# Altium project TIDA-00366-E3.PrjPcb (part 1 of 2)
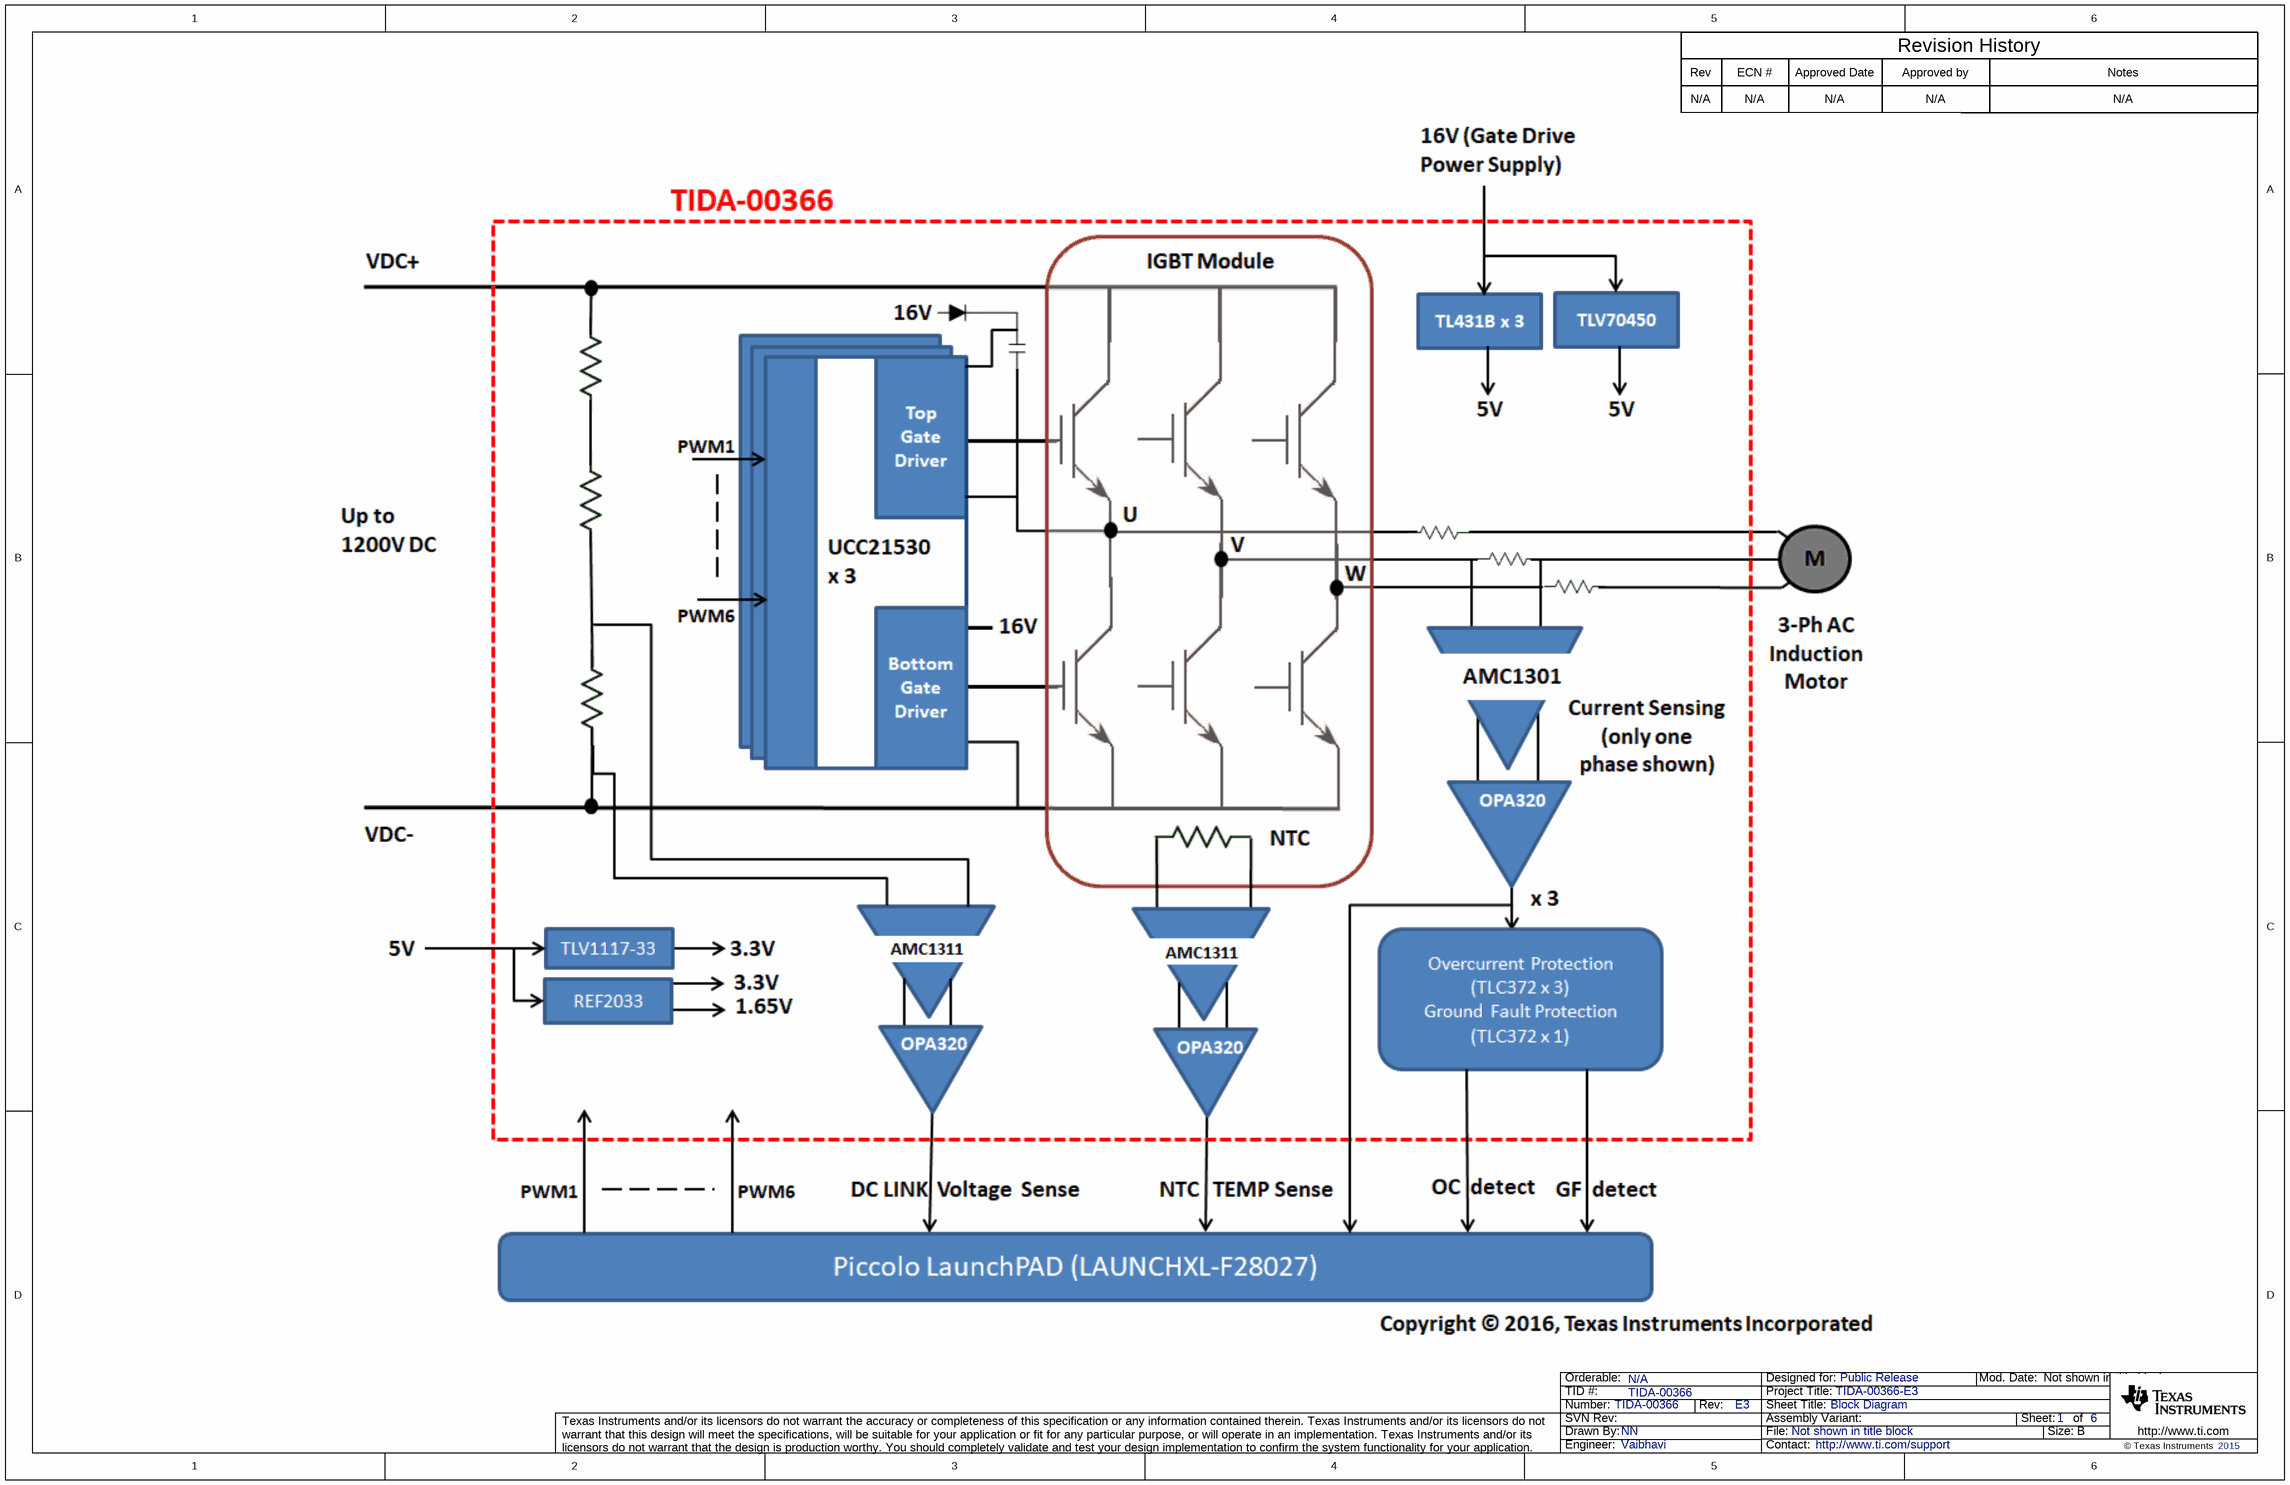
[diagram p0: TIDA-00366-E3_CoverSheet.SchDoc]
CopyrightYear: 2015; EVM_Orderable: N/A; PCB_Layout: Avinash N; PCB_Rev: E3; PRJ_Customer: Public Release; PRJ_Engineer: Vaibhavi; PRJ_Number: TIDA-00366; PRJ_Title: TIDA-00366-E3; SCH_Rev: E3; TechSupport: http://www.ti.com/support; TID: TIDA-00366
6 sheets, 363 parts. Net scope: flat (ports and power ports of the same name join across sheets).
Board file: TIDA-00366-E3.PcbDoc
Sheets:
  TIDA-00366-E3_CoverSheet.SchDoc
  TIDA-00366-E3_Current sense.SchDoc
  TIDA-00366-E3_Gate driver and Module.SchDoc
  TIDA-00366-E3_DC BUS and TEMP Sense.SchDoc
  TIDA-00366-E3_MCU Interface.SchDoc
  TIDA-00366-E3_EVM_Hardware.SchDoc

## Sheet TIDA-00366-E3_CoverSheet.SchDoc: Block Diagram
size 431 x 279 mm; Date: Not shown in title block; ApprovedBy: Not shown in title block; CheckedBy: Not shown in title block; Author: Not shown in title block; CompanyName: Not shown in title block; DrawnBy: NN; Engineer: Not shown in title block; Organization: Not shown in title block; Address1: Not shown in title block; Address2: Not shown in title block; Address3: Not shown in title block; Address4: Not shown in title block; DocumentNumber: 1; Revision: Use project parameter SCH_Rev; SheetNumber: 1; SheetTotal: 6; PageSetup: Record=PageOptions¦CenterHorizontal=True¦CenterVertical=True¦PrintScale=1.00¦XCorrection=1.00¦YCorrection=1.00¦PrintKind=0¦BorderSize=5000000¦LeftOffset=0¦BottomOffset=0¦Orientation=2¦PaperLength=1000¦PaperWidth=1000¦Scale=100¦PaperSource=15¦PrintQuality=600¦MediaType=1¦DitherType=10¦PaperKind=Letter¦PrintScaleMode=1

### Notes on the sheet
- Rev
- N/A
- ECN #
- Approved Date
- Approved by
- Revision History
- Notes

## Sheet TIDA-00366-E3_Current sense.SchDoc: Current Sense
size 431 x 279 mm; Date: Not shown in title block; ApprovedBy: Not shown in title block; CheckedBy: Not shown in title block; Author: Not shown in title block; CompanyName: Not shown in title block; DrawnBy: NN; Engineer: Not shown in title block; Organization: Not shown in title block; Address1: Not shown in title block; Address2: Not shown in title block; Address3: Not shown in title block; Address4: Not shown in title block; DocumentNumber: 1; Revision: Use project parameter SCH_Rev; SheetNumber: 3; SheetTotal: 6; PageSetup: Record=PageOptions¦CenterHorizontal=True¦CenterVertical=True¦PrintScale=1.00¦XCorrection=1.00¦YCorrection=1.00¦PrintKind=0¦BorderSize=5000000¦LeftOffset=0¦BottomOffset=0¦Orientation=2¦PaperLength=1000¦PaperWidth=1000¦Scale=100¦PaperSource=15¦PrintQuality=600¦MediaType=1¦DitherType=10¦PaperKind=Letter¦PrintScaleMode=1
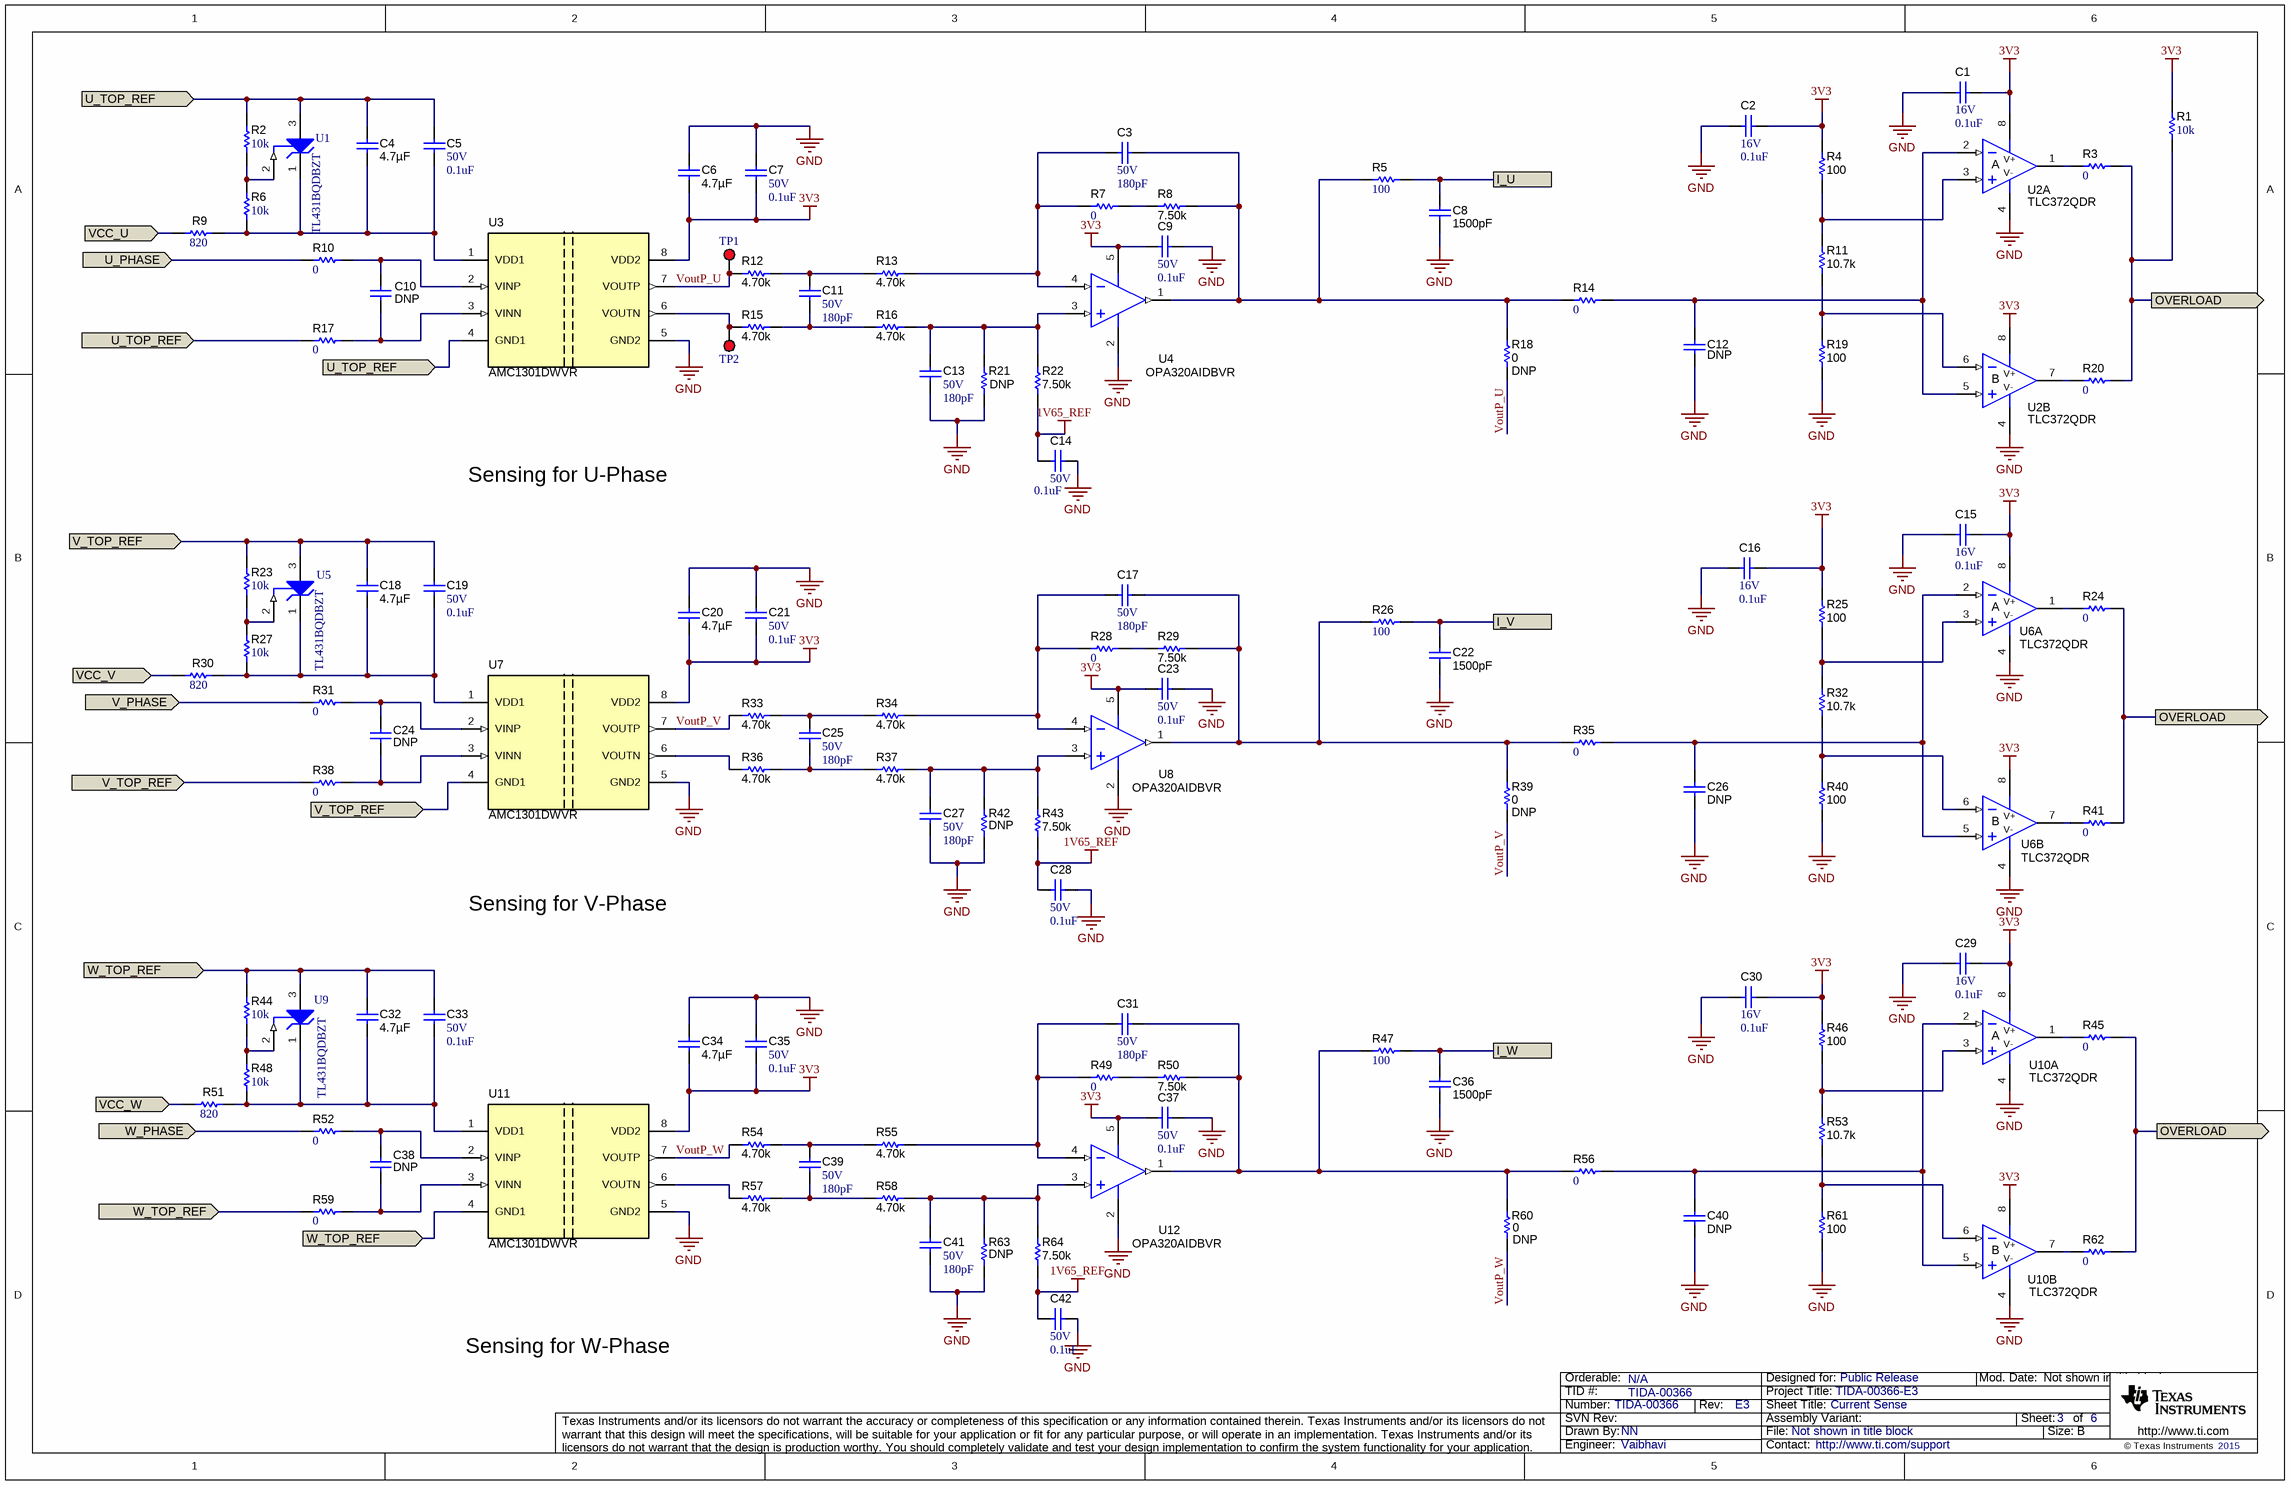
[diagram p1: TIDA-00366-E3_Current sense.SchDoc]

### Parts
C1  VDC_V: 16V  ValueDisplayed: 0.1uF  [0603]  (hidden comment: C0603X104K4RACTU)
C2  VDC_V: 16V  ValueDisplayed: 0.1uF  [0603]  (hidden comment: C0603X104K4RACTU)
C3  VDC_V: 50V  ValueDisplayed: 180pF  [0603]  (hidden comment: GRM1885C1H181JA01D)
C4  ValueDisplayed: 4.7µF  [0805_HV]  (hidden comment: C2012X5R1H475K125AB)
C5  VDC_V: 50V  ValueDisplayed: 0.1uF  [0603]  (hidden comment: GCM188R71H104KA57D)
C6  ValueDisplayed: 4.7µF  [0805_HV]  (hidden comment: C2012X5R1H475K125AB)
C7  VDC_V: 50V  ValueDisplayed: 0.1uF  [0603]  (hidden comment: GCM188R71H104KA57D)
C8  ValueDisplayed: 1500pF  [0603]  (hidden comment: 06031C152JAT2A)
C9  VDC_V: 50V  ValueDisplayed: 0.1uF  [0603]  (hidden comment: GCM188R71H104KA57D)
C10  885012206040  [0603]  (value not drawn)
C11  VDC_V: 50V  ValueDisplayed: 180pF  [0603]  (hidden comment: GRM1885C1H181JA01D)
C12  885012206040  [0603]  (value not drawn)
C13  VDC_V: 50V  ValueDisplayed: 180pF  [0603]  (hidden comment: GRM1885C1H181JA01D)
C14  VDC_V: 50V  ValueDisplayed: 0.1uF  [0603]  (hidden comment: GCM188R71H104KA57D)
C15  VDC_V: 16V  ValueDisplayed: 0.1uF  [0603]  (hidden comment: C0603X104K4RACTU)
C16  VDC_V: 16V  ValueDisplayed: 0.1uF  [0603]  (hidden comment: C0603X104K4RACTU)
C17  VDC_V: 50V  ValueDisplayed: 180pF  [0603]  (hidden comment: GRM1885C1H181JA01D)
C18  ValueDisplayed: 4.7µF  [0805_HV]  (hidden comment: C2012X5R1H475K125AB)
C19  VDC_V: 50V  ValueDisplayed: 0.1uF  [0603]  (hidden comment: GCM188R71H104KA57D)
C20  ValueDisplayed: 4.7µF  [0805_HV]  (hidden comment: C2012X5R1H475K125AB)
C21  VDC_V: 50V  ValueDisplayed: 0.1uF  [0603]  (hidden comment: GCM188R71H104KA57D)
C22  ValueDisplayed: 1500pF  [0603]  (hidden comment: 06031C152JAT2A)
C23  VDC_V: 50V  ValueDisplayed: 0.1uF  [0603]  (hidden comment: GCM188R71H104KA57D)
C24  885012206040  [0603]  (value not drawn)
C25  VDC_V: 50V  ValueDisplayed: 180pF  [0603]  (hidden comment: GRM1885C1H181JA01D)
C26  885012206040  [0603]  (value not drawn)
C27  VDC_V: 50V  ValueDisplayed: 180pF  [0603]  (hidden comment: GRM1885C1H181JA01D)
C28  VDC_V: 50V  ValueDisplayed: 0.1uF  [0603]  (hidden comment: GCM188R71H104KA57D)
C29  VDC_V: 16V  ValueDisplayed: 0.1uF  [0603]  (hidden comment: C0603X104K4RACTU)
C30  VDC_V: 16V  ValueDisplayed: 0.1uF  [0603]  (hidden comment: C0603X104K4RACTU)
C31  VDC_V: 50V  ValueDisplayed: 180pF  [0603]  (hidden comment: GRM1885C1H181JA01D)
C32  ValueDisplayed: 4.7µF  [0805_HV]  (hidden comment: C2012X5R1H475K125AB)
C33  VDC_V: 50V  ValueDisplayed: 0.1uF  [0603]  (hidden comment: GCM188R71H104KA57D)
C34  ValueDisplayed: 4.7µF  [0805_HV]  (hidden comment: C2012X5R1H475K125AB)
C35  VDC_V: 50V  ValueDisplayed: 0.1uF  [0603]  (hidden comment: GCM188R71H104KA57D)
C36  ValueDisplayed: 1500pF  [0603]  (hidden comment: 06031C152JAT2A)
C37  VDC_V: 50V  ValueDisplayed: 0.1uF  [0603]  (hidden comment: GCM188R71H104KA57D)
C38  885012206040  [0603]  (value not drawn)
C39  VDC_V: 50V  ValueDisplayed: 180pF  [0603]  (hidden comment: GRM1885C1H181JA01D)
C40  885012206040  [0603]  (value not drawn)
C41  VDC_V: 50V  ValueDisplayed: 180pF  [0603]  (hidden comment: GRM1885C1H181JA01D)
C42  VDC_V: 50V  ValueDisplayed: 0.1uF  [0603]  (hidden comment: GCM188R71H104KA57D)
R1  ValueDisplayed: 10k  [0603]  (hidden comment: RC0603JR-0710KL)
R2  ValueDisplayed: 10k  [0603]  (hidden comment: RC0603JR-0710KL)
R3  ValueDisplayed: 0  [0603]  (hidden comment: RC0603JR-070RL)
R4  ValueDisplayed: 100  [0603]  (hidden comment: ERA-3AEB101V)
R5  ValueDisplayed: 100  [0603]  (hidden comment: RC0603FR-07100RL)
R6  ValueDisplayed: 10k  [0603]  (hidden comment: RC0603JR-0710KL)
R7  ValueDisplayed: 0  [0603]  (hidden comment: RC0603JR-070RL)
R8  ValueDisplayed: 7.50k  [0603]  (hidden comment: ERJ-3EKF7501V)
R9  ValueDisplayed: 820  [1206]  (hidden comment: CRCW1206820RJNEA)
R10  ValueDisplayed: 0  [0603]  (hidden comment: RC0603JR-070RL)
R11  ValueDisplayed: 10.7k  [0603]  (hidden comment: RG1608P-1072-B-T5)
R12  ValueDisplayed: 4.70k  [0603]  (hidden comment: RC0603FR-074K7L)
R13  ValueDisplayed: 4.70k  [0603]  (hidden comment: RC0603FR-074K7L)
R14  ValueDisplayed: 0  [0603]  (hidden comment: RC0603JR-070RL)
R15  ValueDisplayed: 4.70k  [0603]  (hidden comment: RC0603FR-074K7L)
R16  ValueDisplayed: 4.70k  [0603]  (hidden comment: RC0603FR-074K7L)
R17  ValueDisplayed: 0  [0603]  (hidden comment: RC0603JR-070RL)
R18  ValueDisplayed: 0  [0603]  (hidden comment: CRCW06030000Z0EA)
R19  ValueDisplayed: 100  [0603]  (hidden comment: ERA-3AEB101V)
R20  ValueDisplayed: 0  [0603]  (hidden comment: RC0603JR-070RL)
R21  ERJ-3EKF7501V  [0603]  (value not drawn)
R22  ValueDisplayed: 7.50k  [0603]  (hidden comment: ERJ-3EKF7501V)
R23  ValueDisplayed: 10k  [0603]  (hidden comment: RC0603JR-0710KL)
R24  ValueDisplayed: 0  [0603]  (hidden comment: RC0603JR-070RL)
R25  ValueDisplayed: 100  [0603]  (hidden comment: ERA-3AEB101V)
R26  ValueDisplayed: 100  [0603]  (hidden comment: RC0603FR-07100RL)
R27  ValueDisplayed: 10k  [0603]  (hidden comment: RC0603JR-0710KL)
R28  ValueDisplayed: 0  [0603]  (hidden comment: RC0603JR-070RL)
R29  ValueDisplayed: 7.50k  [0603]  (hidden comment: ERJ-3EKF7501V)
R30  ValueDisplayed: 820  [1206]  (hidden comment: CRCW1206820RJNEA)
R31  ValueDisplayed: 0  [0603]  (hidden comment: RC0603JR-070RL)
R32  ValueDisplayed: 10.7k  [0603]  (hidden comment: RG1608P-1072-B-T5)
R33  ValueDisplayed: 4.70k  [0603]  (hidden comment: RC0603FR-074K7L)
R34  ValueDisplayed: 4.70k  [0603]  (hidden comment: RC0603FR-074K7L)
R35  ValueDisplayed: 0  [0603]  (hidden comment: RC0603JR-070RL)
R36  ValueDisplayed: 4.70k  [0603]  (hidden comment: RC0603FR-074K7L)
R37  ValueDisplayed: 4.70k  [0603]  (hidden comment: RC0603FR-074K7L)
R38  ValueDisplayed: 0  [0603]  (hidden comment: RC0603JR-070RL)
R39  ValueDisplayed: 0  [0603]  (hidden comment: CRCW06030000Z0EA)
R40  ValueDisplayed: 100  [0603]  (hidden comment: ERA-3AEB101V)
R41  ValueDisplayed: 0  [0603]  (hidden comment: RC0603JR-070RL)
R42  ERJ-3EKF7501V  [0603]  (value not drawn)
R43  ValueDisplayed: 7.50k  [0603]  (hidden comment: ERJ-3EKF7501V)
R44  ValueDisplayed: 10k  [0603]  (hidden comment: RC0603JR-0710KL)
R45  ValueDisplayed: 0  [0603]  (hidden comment: RC0603JR-070RL)
R46  ValueDisplayed: 100  [0603]  (hidden comment: ERA-3AEB101V)
R47  ValueDisplayed: 100  [0603]  (hidden comment: RC0603FR-07100RL)
R48  ValueDisplayed: 10k  [0603]  (hidden comment: RC0603JR-0710KL)
R49  ValueDisplayed: 0  [0603]  (hidden comment: RC0603JR-070RL)
R50  ValueDisplayed: 7.50k  [0603]  (hidden comment: ERJ-3EKF7501V)
R51  ValueDisplayed: 820  [1206]  (hidden comment: CRCW1206820RJNEA)
R52  ValueDisplayed: 0  [0603]  (hidden comment: RC0603JR-070RL)
R53  ValueDisplayed: 10.7k  [0603]  (hidden comment: RG1608P-1072-B-T5)
R54  ValueDisplayed: 4.70k  [0603]  (hidden comment: RC0603FR-074K7L)
R55  ValueDisplayed: 4.70k  [0603]  (hidden comment: RC0603FR-074K7L)
R56  ValueDisplayed: 0  [0603]  (hidden comment: RC0603JR-070RL)
R57  ValueDisplayed: 4.70k  [0603]  (hidden comment: RC0603FR-074K7L)
R58  ValueDisplayed: 4.70k  [0603]  (hidden comment: RC0603FR-074K7L)
R59  ValueDisplayed: 0  [0603]  (hidden comment: RC0603JR-070RL)
R60  ValueDisplayed: 0  [0603]  (hidden comment: CRCW06030000Z0EA)
R61  ValueDisplayed: 100  [0603]  (hidden comment: ERA-3AEB101V)
R62  ValueDisplayed: 0  [0603]  (hidden comment: RC0603JR-070RL)
R63  ERJ-3EKF7501V  [0603]  (value not drawn)
R64  ValueDisplayed: 7.50k  [0603]  (hidden comment: ERJ-3EKF7501V)
TP1  5000  [Keystone5000]  (value not drawn)
TP2  5000  [Keystone5000]  (value not drawn)
U1  TL431BQDBZT  [DBZ0003A_N]
U2  TLC372QDR  [D0008A_N]  (parts A,B of 2)
U3  AMC1301DWVR  [DWV0008A]
U4  OPA320AIDBVR  [DBV0005A_N]
U5  TL431BQDBZT  [DBZ0003A_N]
U6  TLC372QDR  [D0008A_N]  (parts A,B of 2)
U7  AMC1301DWVR  [DWV0008A]
U8  OPA320AIDBVR  [DBV0005A_N]
U9  TL431BQDBZT  [DBZ0003A_N]
U10  TLC372QDR  [D0008A_N]  (parts A,B of 2)
U11  AMC1301DWVR  [DWV0008A]
U12  OPA320AIDBVR  [DBV0005A_N]

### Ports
I_U, I_V, I_W, OVERLOAD (out), U_PHASE (in), U_TOP_REF (in), V_PHASE (in), V_TOP_REF (in), VCC_U (in), VCC_V (in), VCC_W (in), W_PHASE (in), W_TOP_REF (in)

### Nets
1V65_REF: C14.2 C28.2 C42.2 R22.1 R43.1 R64.1
3V3: C1.1 C2.1 C6.2 C7.2 C9.2 C15.1 C16.1 C20.2 C21.2 C23.2 C29.1 C30.1 C34.2 C35.2 C37.2 R1.2 R4.2 R25.2 R46.2 U2.8(V+) U3.8(VDD2) U4.5(V+) U6.8(V+) U7.8(VDD2) U8.5(V+) U10.8(V+) U11.8(VDD2) U12.5(V+)  [project net VCCI]
GND: C1.2 C2.2 C6.1 C7.1 C8.2 C9.1 C12.2 C13.2 C14.1 C15.2 C16.2 C20.1 C21.1 C22.2 C23.1 C26.2 C27.2 C28.1 C29.2 C30.2 C34.1 C35.1 C36.2 C37.1 C40.2 C41.2 C42.1 R19.1 R21.1 R40.1 R42.1 R61.1 R63.1 U2.4(V-) U3.5(GND2) U4.2(V-) U6.4(V-) U7.5(GND2) U8.2(V-) U10.4(V-) U11.5(GND2) U12.2(V-)
I_U: C8.1 R5.2 ; port I_U
I_V: C22.1 R26.2 ; port I_V
I_W: C36.1 R47.2 ; port I_W
OVERLOAD: R1.1 R3.2 R20.2 R24.2 R41.2 R45.2 R62.2 ; port OVERLOAD
U_PHASE: R10.1 ; port U_PHASE
U_TOP_REF: C4.1 C5.1 R2.2 R17.1 U1.3(ANODE) U3.4(GND1) ; port U_TOP_REF
V_PHASE: R31.1 ; port V_PHASE
V_TOP_REF: C18.1 C19.1 R23.2 R38.1 U5.3(ANODE) U7.4(GND1) ; port V_TOP_REF
VCC_U: R9.1 ; port VCC_U
VCC_V: R30.1 ; port VCC_V
VCC_W: R51.1 ; port VCC_W
VoutP_U: R12.1 R18.1 TP1.1 U3.7(VOUTP)
VoutP_V: R33.1 R39.1 U7.7(VOUTP)
VoutP_W: R54.1 R60.1 U11.7(VOUTP)
W_PHASE: R52.1 ; port W_PHASE
W_TOP_REF: C32.1 C33.1 R44.2 R59.1 U9.3(ANODE) U11.4(GND1) ; port W_TOP_REF
NetC3_1: C3.1 R5.1 R8.2 R14.1 R18.2 U4.1(OUT)
NetC3_2: C3.2 R7.1 R13.2 U4.4(IN-)
NetC4_2: C4.2 C5.2 R6.1 R9.2 U1.1(CATHODE) U3.1(VDD1)
NetC10_1: C10.1 R10.2 U3.2(VINP)
NetC10_2: C10.2 R17.2 U3.3(VINN)
NetC11_1: C11.1 R12.2 R13.1
NetC11_2: C11.2 R15.2 R16.1
NetC12_1: C12.1 R14.2 U2.2(IN-) U2.5(IN+)
NetC13_1: C13.1 R16.2 R21.2 R22.2 U4.3(IN+)
NetC17_1: C17.1 R26.1 R29.2 R35.1 R39.2 U8.1(OUT)
NetC17_2: C17.2 R28.1 R34.2 U8.4(IN-)
NetC18_2: C18.2 C19.2 R27.1 R30.2 U5.1(CATHODE) U7.1(VDD1)
NetC24_1: C24.1 R31.2 U7.2(VINP)
NetC24_2: C24.2 R38.2 U7.3(VINN)
NetC25_1: C25.1 R33.2 R34.1
NetC25_2: C25.2 R36.2 R37.1
NetC26_1: C26.1 R35.2 U6.2(IN-) U6.5(IN+)
NetC27_1: C27.1 R37.2 R42.2 R43.2 U8.3(IN+)
NetC31_1: C31.1 R47.1 R50.2 R56.1 R60.2 U12.1(OUT)
NetC31_2: C31.2 R49.1 R55.2 U12.4(IN-)
NetC32_2: C32.2 C33.2 R48.1 R51.2 U9.1(CATHODE) U11.1(VDD1)
NetC38_1: C38.1 R52.2 U11.2(VINP)
NetC38_2: C38.2 R59.2 U11.3(VINN)
NetC39_1: C39.1 R54.2 R55.1
NetC39_2: C39.2 R57.2 R58.1
NetC40_1: C40.1 R56.2 U10.2(IN-) U10.5(IN+)
NetC41_1: C41.1 R58.2 R63.2 R64.2 U12.3(IN+)
NetR2_1: R2.1 R6.2 U1.2(REF)
NetR3_1: R3.1 U2.1(OUT)
NetR4_1: R4.1 R11.2 U2.3(IN+)
NetR7_2: R7.2 R8.1
NetR11_1: R11.1 R19.2 U2.6(IN-)
NetR15_1: R15.1 TP2.1 U3.6(VOUTN)
NetR20_1: R20.1 U2.7(OUT)
NetR23_1: R23.1 R27.2 U5.2(REF)
NetR24_1: R24.1 U6.1(OUT)
NetR25_1: R25.1 R32.2 U6.3(IN+)
NetR28_2: R28.2 R29.1
NetR32_1: R32.1 R40.2 U6.6(IN-)
NetR36_1: R36.1 U7.6(VOUTN)
NetR41_1: R41.1 U6.7(OUT)
NetR44_1: R44.1 R48.2 U9.2(REF)
NetR45_1: R45.1 U10.1(OUT)
NetR46_1: R46.1 R53.2 U10.3(IN+)
NetR49_2: R49.2 R50.1
NetR53_1: R53.1 R61.2 U10.6(IN-)
NetR57_1: R57.1 U11.6(VOUTN)
NetR62_1: R62.1 U10.7(OUT)

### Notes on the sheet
- Sensing for U-Phase
- Sensing for V-Phase
- Sensing for W-Phase

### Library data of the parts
C1 C2 C15 C16 C29 C30 = CMP-0006980-4: CAP, CERM, 0.1 uF, 16 V, +/- 10%, X7R, 0603; Manufacturer: Kemet; TaMin_C: -55°C; Polarized: N; SizeAreaWB_mm2: 4.68; Value1: Unknown; U/M: EA; Value: 0.1uF; TaMax_C: 125°C; SizeZ_mm: 1; SizeX_mm: 1.6; SizeY_mm: 0.8; SizeArea_mm2: 1.28; Cap_F: 100nF; AEC Category: Q200
C3 C11 C13 C17 C25 C27 C31 C39 C41 = CMP-0007191-4: CAP, CERM, 180 pF, 50 V, +/- 5%, C0G/NP0, 0603; Manufacturer: MuRata; TaMin_C: -55°C; Polarized: N; SizeAreaWB_mm2: 4.68; Value1: Unknown; U/M: EA; Value: 180pF; TaMax_C: 125°C; SizeZ_mm: 1; SizeX_mm: 1.6; SizeY_mm: 0.8; SizeArea_mm2: 1.28; AEC Category: Q200
C4 C6 C18 C20 C32 C34 = C2012X5R1H475K125AB: CAP, CERM, 4.7 µF, 50 V, +/- 10%, X5R, 0805; Manufacturer: TDK; Polarized: N; CompType: Capacitor; Value: 4.7uF; U/M: EA; Cap_F: 0.0000047; Tolerance_%: 10; Value1: Unknown; VDC_V: 50; Value2: 50V; TaMin_C: -55; TaMax_C: 85; Cap_Case: 0805; AEC Category: Q200
C5 C7 C9 C14 C19 C21 C23 C28 C33 C35 C37 C42 = CMP-0007144-4: CAP, CERM, 0.1 uF, 50 V, +/- 10%, X7R, 0603; Manufacturer: MuRata; TaMin_C: -55°C; ESR_ohm: 0.02; Polarized: N; SizeAreaWB_mm2: 4.68; Value1: 0.02 ohm; U/M: EA; Value: 0.1uF; TaMax_C: 125°C; SizeZ_mm: 1; SizeX_mm: 1.6; SizeY_mm: 0.8; SizeArea_mm2: 1.28; Cap_F: 100nF; IRMS_A: 1.84A; AEC Category: Q200
C8 C22 C36 = 06031C152JAT2A: CAP, CERM, 1500 pF, 100 V, +/- 5%, X7R, 0603; Manufacturer: AVX; Polarized: N; CompType: Capacitor; Value: 1500pF; U/M: EA; Cap_F: 0.0000000015; Tolerance_%: 5; ESR_ohm: 0.229; Value1: 0.229 ohm; VDC_V: 100; Value2: 100V; TaMin_C: -55; TaMax_C: 125; AEC Category: Q200
C10 C12 C24 C26 C38 C40 = 885012206040: CAP, CERM, 0.01 µF, 16 V, +/- 10%, X7R, 0603; Manufacturer: Wurth Elektronik; Polarized: N; CompType: Capacitor; Value: 0.01uF; ValueDisplayed: 0.01µF; U/M: EA; Cap_F: 0.00000001; Tolerance_%: 10; Value1: Unknown; VDC_V: 16; Value2: 16V; TaMin_C: -55; TaMax_C: 125; AEC Category: Q200
R1 R2 R6 R23 R27 R44 R48 = CMP-0025886-5: RES, 10 k, 5%, 0.1 W, 0603; Manufacturer: Yageo; Power_W: 100mW; TempCo: 100 ppm/C; Value_Code: 10k0; Value: 10k; EIA_Code: E24; SizeX_mm: 1.6; SizeY_mm: 0.8; SizeZ_mm: 1; Value2: 0.1W; SizeArea_mm2: 1.28; AEC Qualified: N; VDC_V: 75V; AEC Category: Q200; SizeAreaWB_mm2: 4.68
R3 R7 R10 R14 R17 R20 R24 R28 R31 R35 R38 R41 R45 R49 R52 R56 R59 R62 = CMP-0025885-5: RES, 0, 5%, 0.1 W, 0603; Manufacturer: Yageo; Power_W: 100mW; TempCo: 200 ppm/C; Value_Code: 0000; Value: 0; EIA_Code: E24; SizeX_mm: 1.6; SizeZ_mm: 1; Value2: 0.1W; SizeArea_mm2: 1.28; AEC Qualified: N; VDC_V: 75V; AEC Category: Q200; SizeY_mm: 0.8; SizeAreaWB_mm2: 4.68
R4 R19 R25 R40 R46 R61 = ERA-3AEB101V: RES, 100, 0.1%, 0.1 W, AEC-Q200 Grade 0, 0603; Manufacturer: Panasonic; CompType: Resistor; Value: 100; Value_Code: 100R; Tolerance_%: 0.1; Value2: 0.1W; VDC_V: 75; TempCo: 25 ppm/C; EIA_Code: E192; U/M: EA; AEC Category: Q200; AEC Qualified: Y; AEC Grade: 0; SizeArea_mm2: 1.28; SizeX_mm: 1.6; SizeY_mm: 0.8; SizeZ_mm: 1
R5 R26 R47 = CMP-0022736-4: RES, 100, 1%, 0.1 W, 0603; Manufacturer: Yageo; Power_W: 100mW; TempCo: 100 ppm/C; Value_Code: 100R; Value: 100; EIA_Code: E96; SizeX_mm: 1.6; SizeY_mm: 0.8; SizeZ_mm: 1; Value2: 0.1W; SizeArea_mm2: 1.28; AEC Qualified: N; VDC_V: 75V; AEC Category: Q200; SizeAreaWB_mm2: 4.68
R8 R29 R50 = ERJ-3EKF7501V: RES, 7.50 k, 1%, 0.1 W, 0603; Manufacturer: Panasonic; CompType: Resistor; Value: 7.50k; Res_ohm: 7500; Value_Code: 7k50; Tolerance_%: 1; Power_W: 0.1; Value2: 0.1W; VDC_V: 75; TempCo: 100 ppm/C; EIA_Code: E96; U/M: EA; AEC Category: Q200
R9 R30 R51 = CMP-0018732-3: RES, 820, 5%, 0.25 W, AEC-Q200 Grade 0, 1206; Manufacturer: Vishay-Dale; Power_W: 250mW; TempCo: 200 ppm/C; Value_Code: 820R; Value: 820; EIA_Code: E24; SizeX_mm: 3.2; SizeY_mm: 1.6; SizeZ_mm: 1.35; Value2: 0.25W; SizeArea_mm2: 5.12; AEC Qualified: Y; VDC_V: 200V; AEC Category: Q200; AEC Grade: 0
R11 R32 R53 = RG1608P-1072-B-T5: RES, 10.7 k, 0.1%, 0.1 W, 0603; Manufacturer: Susumu Co Ltd; CompType: Resistor; Value: 10.7k; Res_ohm: 10700; Value_Code: 10k7; Tolerance_%: 0.1; Value2: 0.1W; VDC_V: 75; TempCo: 25 ppm/C; EIA_Code: E192; U/M: EA; AEC Category: Q200; SizeArea_mm2: 1.28; SizeX_mm: 1.6; SizeY_mm: 0.8; SizeZ_mm: 1
R12 R13 R15 R16 R33 R34 R36 R37 R54 R55 R57 R58 = RC0603FR-074K7L: RES, 4.70 k, 1%, 0.1 W, 0603; Manufacturer: Yageo America; CompType: Resistor; Value: 4.70k; Res_ohm: 4700; Value_Code: 4k70; Tolerance_%: 1; Power_W: 0.1; Value2: 0.1W; VDC_V: 150; TempCo: 200 ppm/C; U/M: EA; AEC Category: Q200
R18 R39 R60 = CRCW06030000Z0EA: RES, 0, 5%, 0.1 W, 0603; Manufacturer: Vishay-Dale; CompType: Resistor; Value: 0; Value_Code: 0000; Tolerance_%: 5; Power_W: 0.1; Value2: 0.1W; VDC_V: 75; TempCo: 200 ppm/C; EIA_Code: E24; U/M: EA; AEC Category: Q200
R21 R22 R42 R43 R63 R64 = ERJ-3EKF7501V: RES, 7.50 k, 1%, 0.1 W, 0603; Manufacturer: Panasonic; CompType: Resistor; Value: 7.50k; Res_ohm: 7500; Value_Code: 7k50; Tolerance_%: 1; Power_W: 0.1; Value2: 0.1W; VDC_V: 75; TempCo: 100 ppm/C; EIA_Code: E96; U/M: EA; AEC Category: Q200; SizeArea_mm2: 1.28; SizeX_mm: 1.6; SizeY_mm: 0.8
TP1 TP2 = 5000: Test Point, Miniature, Red, TH; Manufacturer: Keystone; CompType: Test Point Loop; ContactFinish: Silver
U1 U5 U9 = TL431BQDBZT: Adjustable Precision Shunt Regulator, 34 ppm / degC, 100 mA, -40 to 125 degC, 3-pin SOT-23 (DBZ), Green (RoHS & no Sb/Br); Manufacturer: Texas Instruments; Alternate PartNumber: Equivalent; Initial Accuracy @ 25/deg C(%): 0.5; Iout/Iz(Max)(mA): 100; Min Iz for Regulation(uA): 600; Rating: Catalog; SubFamily: Shunt Voltage Reference; Temp Coeff(Max)(ppm/ degree C): 92; Temp Coeff(Typ)(ppm/ degree C): 34; VO Adj(Max)(V): 36; VO Adj(Min)(V): 2.495
U2 U6 U10 = TLC372QDR: LinCMOS Dual Differential Comparators, D0008A; Manufacturer: Texas Instruments; SymbolCreator: a0411947; CompType: IC; U/M: EA
U3 U7 U11 = AMC1301DWVR: 200 kHz, Fully-Differential Isolation Amplifier, DWV0008A; Manufacturer: Texas Instruments; SymbolCreator: Altium; CompType: IC; U/M: EA
U4 U8 U12 = OPA320AIDBVR: Precision, 20 MHz, 0.9 pA Ib, RRIO, CMOS Operational Amplifier, 1.8 to 5.5 V, -40 to 125 degC, 5-pin SOT23 (DBV0005A), Green (RoHS & no Sb/Br); Manufacturer: Texas Instruments; Alternate PartNumber: Equivalent; CMRR(Min)(dB): 100; IIB(Max)(pA): 0.9; Iq per channel(Max)(mA): 1.75; Number of Channels: 2; Offset Drift(Typ)(uV/C): 1.5; Slew Rate(Typ)(V/us): 10; Sub Family: High Output Current Amplifier (>=50mA), Low Input Bias Current Amp (<=10pA), Low Noise Amp (<=10nV/rtHz), Low Offset Voltage Amplifier (<=500uV), Low Supply Voltage Amplifier (<=2.7V), Precision Amplifier; Total Supply Voltage(Max)(+5V is 5, +/-5V is 10): 5.5; Total Supply Voltage(Min)(+5V is 5, +/-5V is 10): 1.8; Vio (25C)(Max)(mV): 0.15; Vn at 1kHz(Typ)(nV/rtHz): 8.5

## Sheet TIDA-00366-E3_Gate driver and Module.SchDoc: Gate-drivers, IGBT module, DC Link
size 431 x 279 mm; Date: Not shown in title block; ApprovedBy: Not shown in title block; CheckedBy: Not shown in title block; Author: Not shown in title block; CompanyName: Not shown in title block; DrawnBy: NN; Engineer: Not shown in title block; Organization: Not shown in title block; Address1: Not shown in title block; Address2: Not shown in title block; Address3: Not shown in title block; Address4: Not shown in title block; DocumentNumber: 1; Revision: Use project parameter SCH_Rev; SheetNumber: 2; SheetTotal: 6; PageSetup: Record=PageOptions¦CenterHorizontal=True¦CenterVertical=True¦PrintScale=1.00¦XCorrection=1.00¦YCorrection=1.00¦PrintKind=0¦BorderSize=5000000¦LeftOffset=0¦BottomOffset=0¦Orientation=2¦PaperLength=1000¦PaperWidth=1000¦Scale=100¦PaperSource=15¦PrintQuality=600¦MediaType=1¦DitherType=10¦PaperKind=Letter¦PrintScaleMode=1
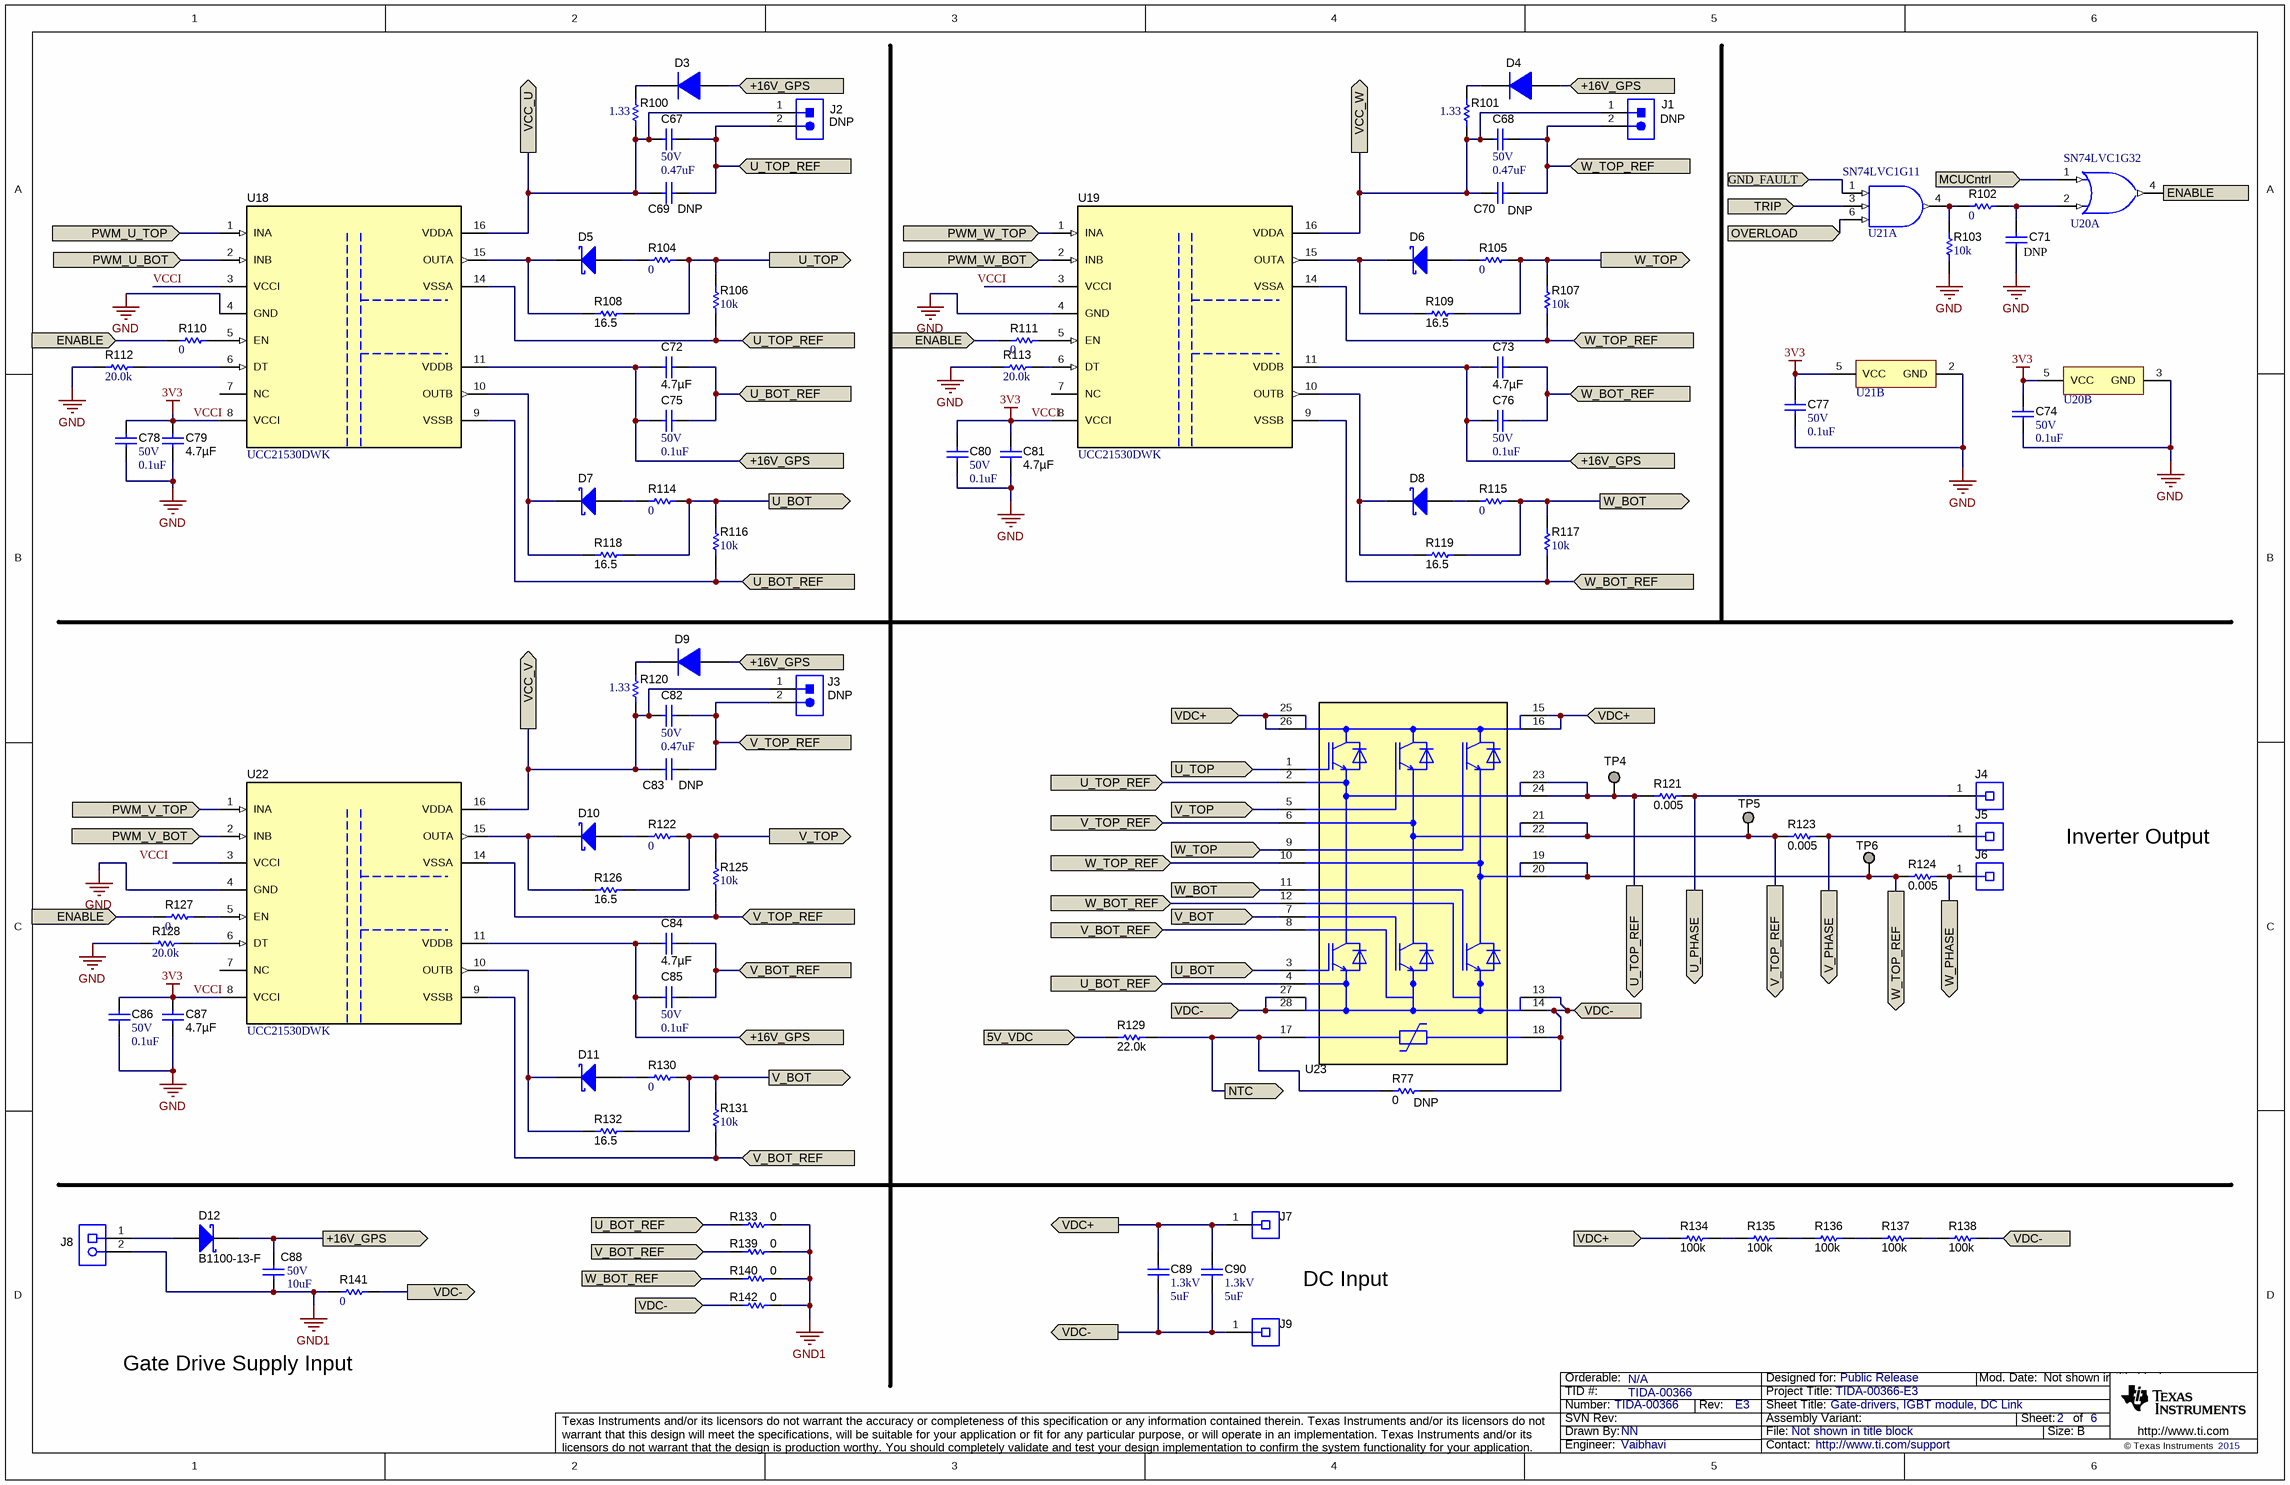
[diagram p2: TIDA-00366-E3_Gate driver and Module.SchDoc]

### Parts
C67  VDC_V: 50V  ValueDisplayed: 0.47uF  [0603]  (hidden comment: C1608X7R1H474K080AC)
C68  VDC_V: 50V  ValueDisplayed: 0.47uF  [0603]  (hidden comment: C1608X7R1H474K080AC)
C69  C2012X5R1H475K125AB  [0805_HV]  (value not drawn)
C70  C2012X5R1H475K125AB  [0805_HV]  (value not drawn)
C71  885012206040  [0603]  (value not drawn)
C72  ValueDisplayed: 4.7µF  [0805_HV]  (hidden comment: C2012X5R1H475K125AB)
C73  ValueDisplayed: 4.7µF  [0805_HV]  (hidden comment: C2012X5R1H475K125AB)
C74  VDC_V: 50V  ValueDisplayed: 0.1uF  [0603]  (hidden comment: GCM188R71H104KA57D)
C75  VDC_V: 50V  ValueDisplayed: 0.1uF  [0603]  (hidden comment: GCM188R71H104KA57D)
C76  VDC_V: 50V  ValueDisplayed: 0.1uF  [0603]  (hidden comment: GCM188R71H104KA57D)
C77  VDC_V: 50V  ValueDisplayed: 0.1uF  [0603]  (hidden comment: GCM188R71H104KA57D)
C78  VDC_V: 50V  ValueDisplayed: 0.1uF  [0603]  (hidden comment: GCM188R71H104KA57D)
C79  ValueDisplayed: 4.7µF  [0805_HV]  (hidden comment: C2012X5R1H475K125AB)
C80  VDC_V: 50V  ValueDisplayed: 0.1uF  [0603]  (hidden comment: GCM188R71H104KA57D)
C81  ValueDisplayed: 4.7µF  [0805_HV]  (hidden comment: C2012X5R1H475K125AB)
C82  VDC_V: 50V  ValueDisplayed: 0.47uF  [0603]  (hidden comment: C1608X7R1H474K080AC)
C83  C2012X5R1H475K125AB  [0805_HV]  (value not drawn)
C84  ValueDisplayed: 4.7µF  [0805_HV]  (hidden comment: C2012X5R1H475K125AB)
C85  VDC_V: 50V  ValueDisplayed: 0.1uF  [0603]  (hidden comment: GCM188R71H104KA57D)
C86  VDC_V: 50V  ValueDisplayed: 0.1uF  [0603]  (hidden comment: GCM188R71H104KA57D)
C87  ValueDisplayed: 4.7µF  [0805_HV]  (hidden comment: C2012X5R1H475K125AB)
C88  VDC_V: 50V  ValueDisplayed: 10uF  [1206_180]  (hidden comment: GRT31CR61H106KE01L)
C89  VDC_V: 1.3kV  ValueDisplayed: 5uF  [B32774_3150x2200x3650]  (hidden comment: B32774D1505K)
C90  VDC_V: 1.3kV  ValueDisplayed: 5uF  [B32774_3150x2200x3650]  (hidden comment: B32774D1505K)
D3  BYG23T-M3/TR  [SMA]  (value not drawn)
D4  BYG23T-M3/TR  [SMA]  (value not drawn)
D5  MSS2P3-M3/89A  [MicroSMP]  (value not drawn)
D6  MSS2P3-M3/89A  [MicroSMP]  (value not drawn)
D7  MSS2P3-M3/89A  [MicroSMP]  (value not drawn)
D8  MSS2P3-M3/89A  [MicroSMP]  (value not drawn)
D9  BYG23T-M3/TR  [SMA]  (value not drawn)
D10  MSS2P3-M3/89A  [MicroSMP]  (value not drawn)
D11  MSS2P3-M3/89A  [MicroSMP]  (value not drawn)
D12  B1100-13-F  [SMA]
J1  800-10-002-10-001000  [Mill-Max_800-10-002-10-001000]  (value not drawn)
J2  800-10-002-10-001000  [Mill-Max_800-10-002-10-001000]  (value not drawn)
J3  800-10-002-10-001000  [Mill-Max_800-10-002-10-001000]  (value not drawn)
J4  7461086  [Wurth_7461086]  (value not drawn)
J5  7461086  [Wurth_7461086]  (value not drawn)
J6  7461086  [Wurth_7461086]  (value not drawn)
J7  7461086  [Wurth_7461086]  (value not drawn)
J8  282834-2  [TEC_282834-2]  (value not drawn)
J9  7461086  [Wurth_7461086]  (value not drawn)
R77  ValueDisplayed: 0  [0603]  (hidden comment: CRCW06030000Z0EA)
R100  ValueDisplayed: 1.33  [0805_HV]  (hidden comment: RC0805FR-071R33L)
R101  ValueDisplayed: 1.33  [0805_HV]  (hidden comment: RC0805FR-071R33L)
R102  ValueDisplayed: 0  [0603]  (hidden comment: RC0603JR-070RL)
R103  ValueDisplayed: 10k  [0603]  (hidden comment: RC0603JR-0710KL)
R104  ValueDisplayed: 0  [1206]  (hidden comment: ERJ-8GEY0R00V)
R105  ValueDisplayed: 0  [1206]  (hidden comment: ERJ-8GEY0R00V)
R106  ValueDisplayed: 10k  [0603]  (hidden comment: RC0603JR-0710KL)
R107  ValueDisplayed: 10k  [0603]  (hidden comment: RC0603JR-0710KL)
R108  ValueDisplayed: 16.5  [1206]  (hidden comment: CRCW120616R5FKEA)
R109  ValueDisplayed: 16.5  [1206]  (hidden comment: CRCW120616R5FKEA)
R110  ValueDisplayed: 0  [0603]  (hidden comment: RC0603JR-070RL)
R111  ValueDisplayed: 0  [0603]  (hidden comment: RC0603JR-070RL)
R112  ValueDisplayed: 20.0k  [0603]  (hidden comment: RC0603FR-0720KL)
R113  ValueDisplayed: 20.0k  [0603]  (hidden comment: RC0603FR-0720KL)
R114  ValueDisplayed: 0  [1206]  (hidden comment: ERJ-8GEY0R00V)
R115  ValueDisplayed: 0  [1206]  (hidden comment: ERJ-8GEY0R00V)
R116  ValueDisplayed: 10k  [0603]  (hidden comment: RC0603JR-0710KL)
R117  ValueDisplayed: 10k  [0603]  (hidden comment: RC0603JR-0710KL)
R118  ValueDisplayed: 16.5  [1206]  (hidden comment: CRCW120616R5FKEA)
R119  ValueDisplayed: 16.5  [1206]  (hidden comment: CRCW120616R5FKEA)
R120  ValueDisplayed: 1.33  [0805_HV]  (hidden comment: RC0805FR-071R33L)
R121  ValueDisplayed: 0.005  [PWR44412-2SD]  (hidden comment: PWR4412-2SDR0050F)
R122  ValueDisplayed: 0  [1206]  (hidden comment: ERJ-8GEY0R00V)
R123  ValueDisplayed: 0.005  [PWR44412-2SD]  (hidden comment: PWR4412-2SDR0050F)
R124  ValueDisplayed: 0.005  [PWR44412-2SD]  (hidden comment: PWR4412-2SDR0050F)
R125  ValueDisplayed: 10k  [0603]  (hidden comment: RC0603JR-0710KL)
R126  ValueDisplayed: 16.5  [1206]  (hidden comment: CRCW120616R5FKEA)
R127  ValueDisplayed: 0  [0603]  (hidden comment: RC0603JR-070RL)
R128  ValueDisplayed: 20.0k  [0603]  (hidden comment: RC0603FR-0720KL)
R129  ValueDisplayed: 22.0k  [0603]  (hidden comment: ERJ-3EKF2202V)
R130  ValueDisplayed: 0  [1206]  (hidden comment: ERJ-8GEY0R00V)
R131  ValueDisplayed: 10k  [0603]  (hidden comment: RC0603JR-0710KL)
R132  ValueDisplayed: 16.5  [1206]  (hidden comment: CRCW120616R5FKEA)
R133  ValueDisplayed: 0  [0805_HV]  (hidden comment: CRCW08050000Z0EA)
R134  ValueDisplayed: 100k  [1206]  (hidden comment: CRCW1206100KJNEA)
R135  ValueDisplayed: 100k  [1206]  (hidden comment: CRCW1206100KJNEA)
R136  ValueDisplayed: 100k  [1206]  (hidden comment: CRCW1206100KJNEA)
R137  ValueDisplayed: 100k  [1206]  (hidden comment: CRCW1206100KJNEA)
R138  ValueDisplayed: 100k  [1206]  (hidden comment: CRCW1206100KJNEA)
R139  ValueDisplayed: 0  [0805_HV]  (hidden comment: CRCW08050000Z0EA)
R140  ValueDisplayed: 0  [0805_HV]  (hidden comment: CRCW08050000Z0EA)
R141  ValueDisplayed: 0  [1206]  (hidden comment: ERJ-8GEY0R00V)
R142  ValueDisplayed: 0  [0805_HV]  (hidden comment: CRCW08050000Z0EA)
TP4  TESTPOINT  [PAD_100mil-40milhole]  (value not drawn)  (no BOM)
TP5  TESTPOINT  [PAD_100mil-40milhole]  (value not drawn)  (no BOM)
TP6  TESTPOINT  [PAD_100mil-40milhole]  (value not drawn)  (no BOM)
U18  UCC21530DWK  [DWK0014A]
U19  UCC21530DWK  [DWK0014A]
U20  Generic Part Number: SN74LVC1G32  [DBV0005A_N]  (hidden comment: SN74LVC1G32DBVR)  (parts A,B of 2)
U21  Generic Part Number: SN74LVC1G11  [DBV0006A_N]  (hidden comment: SN74LVC1G11DBVR)  (parts A,B of 2)
U22  UCC21530DWK  [DWK0014A]
U23  MIXA60W1200TED  [IXYS_E2]  (value not drawn)

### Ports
5V_VDC (in), +16V_GPS (in), +16V_GPS (out), ENABLE (in), ENABLE (out), GND_FAULT (in), MCUCntrl (in), NTC (out), OVERLOAD (in), PWM_U_BOT (in), PWM_U_TOP (in), PWM_V_BOT (in), PWM_V_TOP (in), PWM_W_BOT (in), PWM_W_TOP (in), TRIP (in), U_BOT (in), U_BOT (out), U_BOT_REF (in), U_PHASE (out), U_TOP (in), U_TOP (out), U_TOP_REF (in), U_TOP_REF (out), V_BOT (in), V_BOT (out), V_BOT_REF (in), V_PHASE (out), V_TOP (in), V_TOP (out), V_TOP_REF (in), V_TOP_REF (out), VCC_U (out), VCC_V (out), VCC_W (out), VDC+ (in), VDC+ (out), VDC- (in), VDC- (out), W_BOT (in), W_BOT (out), W_BOT_REF (in), W_PHASE (out), W_TOP (in), W_TOP (out), W_TOP_REF (in), W_TOP_REF (out)

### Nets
GND: C71.2 C74.2 C77.2 C78.2 C79.2 C80.2 C81.2 C86.2 C87.2 R103.1 R112.1 R113.1 R128.1 U18.4(GND) U19.4(GND) U20.3(GND) U21.2(GND) U22.4(GND)
GND1: C88.2 J8.2 R133.2 R139.2 R140.2 R141.1 R142.2
VCCI: C74.1 C77.1 C78.1 C79.1 C80.1 C81.1 C86.1 C87.1 U18.3(VCCI) U18.8(VCCI) U19.8(VCCI) U20.5(VCC) U21.5(VCC) U22.8(VCCI)  [also labelled 3V3]
5V_VDC: R129.1 ; port 5V_VDC
+16V_GPS: C72.2 C73.2 C75.2 C76.2 C84.2 C85.2 C88.1 D3.2(A) D4.2(A) D9.2(A) D12.1(K) U18.11(VDDB) U19.11(VDDB) U22.11(VDDB) ; port +16V_GPS
ENABLE: R110.1 R111.1 R127.1 U20.4(Y) ; port ENABLE
GND_FAULT: U21.1(A) ; port GND_FAULT
MCUCntrl: U20.1(A) ; port MCUCntrl
NTC: R77.2 R129.2 U23.17 ; port NTC
OVERLOAD: U21.6(C) ; port OVERLOAD
PWM_U_BOT: U18.2(INB) ; port PWM_U_BOT
PWM_U_TOP: U18.1(INA) ; port PWM_U_TOP
PWM_V_BOT: U22.2(INB) ; port PWM_V_BOT
PWM_V_TOP: U22.1(INA) ; port PWM_V_TOP
PWM_W_BOT: U19.2(INB) ; port PWM_W_BOT
PWM_W_TOP: U19.1(INA) ; port PWM_W_TOP
TRIP: U21.3(B) ; port TRIP
U_BOT: R114.2 R116.2 R118.2 U23.3 ; port U_BOT
U_BOT_REF: C72.1 C75.1 R116.1 R133.1 U18.9(VSSB) U23.4 ; port U_BOT_REF
U_PHASE: J4.1 R121.1 ; port U_PHASE
U_TOP: R104.2 R106.2 R108.2 U23.1 ; port U_TOP
U_TOP_REF: C67.1 C69.1 J2.2 R106.1 R121.2 TP4.1 U18.14(VSSA) U23.2 U23.23 U23.24 ; port U_TOP_REF
V_BOT: R130.2 R131.2 R132.2 U23.7 ; port V_BOT
V_BOT_REF: C84.1 C85.1 R131.1 R139.1 U22.9(VSSB) U23.8 ; port V_BOT_REF
V_PHASE: J5.1 R123.2 ; port V_PHASE
V_TOP: R122.2 R125.2 R126.2 U23.5 ; port V_TOP
V_TOP_REF: C82.1 C83.1 J3.2 R123.1 R125.1 TP5.1 U22.14(VSSA) U23.6 U23.21 U23.22 ; port V_TOP_REF
VCC_U: C67.2 C69.2 J2.1 R100.1 U18.16(VDDA) ; port VCC_U
VCC_V: C82.2 C83.2 J3.1 R120.1 U22.16(VDDA) ; port VCC_V
VCC_W: C68.2 C70.2 J1.1 R101.1 U19.16(VDDA) ; port VCC_W
VDC+: C89.1 C90.1 J7.1 R134.1 U23.15 U23.16 U23.25 U23.26 ; port VDC+
VDC-: C89.2 C90.2 J9.1 R77.1 R138.2 R141.2 R142.1 U23.13 U23.14 U23.18 U23.27 U23.28 ; port VDC-
W_BOT: R115.2 R117.2 R119.2 U23.11 ; port W_BOT
W_BOT_REF: C73.1 C76.1 R117.1 R140.1 U19.9(VSSB) U23.12 ; port W_BOT_REF
W_PHASE: J6.1 R124.2 ; port W_PHASE
W_TOP: R105.2 R107.2 R109.2 U23.9 ; port W_TOP
W_TOP_REF: C68.1 C70.1 J1.2 R107.1 R124.1 TP6.1 U19.14(VSSA) U23.10 U23.19 U23.20 ; port W_TOP_REF
NetC71_1: C71.1 R102.2 U20.2(B)
NetD3_1: D3.1(K) R100.2
NetD4_1: D4.1(K) R101.2
NetD5_1: D5.1(K) R108.1 U18.15(OUTA)
NetD5_2: D5.2(A) R104.1
NetD6_1: D6.1(K) R109.1 U19.15(OUTA)
NetD6_2: D6.2(A) R105.1
NetD7_1: D7.1(K) R118.1 U18.10(OUTB)
NetD7_2: D7.2(A) R114.1
NetD8_1: D8.1(K) R119.1 U19.10(OUTB)
NetD8_2: D8.2(A) R115.1
NetD9_1: D9.1(K) R120.2
NetD10_1: D10.1(K) R126.1 U22.15(OUTA)
NetD10_2: D10.2(A) R122.1
NetD11_1: D11.1(K) R132.1 U22.10(OUTB)
NetD11_2: D11.2(A) R130.1
NetD12_2: D12.2(A) J8.1
NetR102_1: R102.1 R103.2 U21.4(Y)
NetR110_2: R110.2 U18.5(EN)
NetR111_2: R111.2 U19.5(EN)
NetR112_2: R112.2 U18.6(DT)
NetR113_2: R113.2 U19.6(DT)
NetR127_2: R127.2 U22.5(EN)
NetR128_2: R128.2 U22.6(DT)
NetR134_2: R134.2 R135.1
NetR135_2: R135.2 R136.1
NetR136_2: R136.2 R137.1
NetR137_2: R137.2 R138.1

Not connected (* = marked no-connect by the designer): U18 7(NC); U19 3(VCCI) 7(NC); U22 3(VCCI) 7(NC)

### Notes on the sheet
- Inverter Output
- DC Input
- Gate Drive Supply Input
- Labels drawn without touching a wire or pin: VCCI

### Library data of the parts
C67 C68 C82 = CMP-0007050-4: CAP, CERM, 0.47 uF, 50 V, +/- 10%, X7R, 0603; Manufacturer: TDK; TaMin_C: -55°C; ESR_ohm: 0.010974; Polarized: N; SizeAreaWB_mm2: 4.68; Value1: 0.010974 ohm; U/M: EA; Value: 0.47uF; TaMax_C: 125°C; SizeZ_mm: 1; SizeX_mm: 1.6; SizeY_mm: 0.8; SizeArea_mm2: 1.28; Cap_F: 470nF; IRMS_A: 1.57483A; AEC Category: Q200
C69 C70 C83 = C2012X5R1H475K125AB: CAP, CERM, 4.7 µF, 50 V, +/- 10%, X5R, 0805; Manufacturer: TDK; Polarized: N; CompType: Capacitor; Value: 4.7uF; ValueDisplayed: 4.7µF; U/M: EA; Cap_F: 0.0000047; Tolerance_%: 10; Value1: Unknown; VDC_V: 50; Value2: 50V; TaMin_C: -55; TaMax_C: 85; Cap_Case: 0805; AEC Category: Q200
C71 = 885012206040: as C10 on sheet TIDA-00366-E3_Current sense
C72 C73 C79 C81 C84 C87 = C2012X5R1H475K125AB: as C4 on sheet TIDA-00366-E3_Current sense
C74-C78 C80 C85 C86 = CMP-0007144-4: as C5 on sheet TIDA-00366-E3_Current sense
C88 = CMP-0009015-2: CAP, CERM, 10 uF, 50 V, +/- 10%, X5R, AEC-Q200 Grade 1, 1206; Manufacturer: MuRata; TaMin_C: -55°C; Polarized: N; SizeAreaWB_mm2: 10.92; Value1: Unknown; U/M: EA; Value: 10uF; TaMax_C: 85°C; SizeZ_mm: 1.8; SizeX_mm: 3.2; SizeY_mm: 1.6; Cap_Case: 1206; SizeArea_mm2: 5.12; AEC Qualified: Y; Cap_F: 10µF; AEC Grade: 1; AEC Category: Q200
C89 C90 = CMP-0012358-3: CAP, Film, 5 uF, 1300 V, +/- 10%, 0.0098 ohm, TH; Manufacturer: TDK; TaMin_C: -40°C; ESR_ohm: 9.8m; Polarized: N; SizeAreaWB_mm2: 804; Value: 5uF; TaMax_C: 105°C; SizeZ_mm: 36.5; SizeX_mm: 31.5; SizeY_mm: 22; Cap_Case: 31.5x22x36.5mm; Value2: 1300V; SizeArea_mm2: 693; Cap_F: 5µF; IRMS_A: 10.5A; AEC Category: Q200
D3 D4 D9 = BYG23T-M3/TR: Diode, Ultrafast, 1300 V, 1 A, SMA; Manufacturer: Vishay-Semiconductor; U/M: EA; Vf_V: 1.9; Value: 1300V; Value1: 1A; Value2: 1.9V; Io_A: 1; Vr_V: 1300; TJmax_C: 150; AEC Category: Q101; AEC Qualified: N
D5-D8 D10 D11 = MSS1P3L-M3/89A: Diode, Schottky, 30 V, 2 A, AEC-Q101, MicroSMP; Manufacturer: Vishay-Semiconductor; U/M: EA; Vf_V: 0.6; Value: 30V; Value1: 2A; Value2: 0.6V; Io_A: 1; Vr_V: 30; TJmax_C: 150; RJC_CperW: 40; AEC Category: Q101; AEC Qualified: Y
D12 = B1100-13-F: Diode, Schottky, 100 V, 1 A, SMA; Manufacturer: Diodes Inc.; U/M: EA; Vf_V: 0.79; Value: 100V; Value1: 1A; Value2: 0.79V; Io_A: 1; Vr_V: 100; TJmax_C: 150; RJC_CperW: 25; AEC Category: Q101
J1-J3 = 800-10-002-10-001000: Header, 100mil, 2x1, TH; Manufacturer: Mill-Max; SymbolCreator: a0412235
J4-J7 J9 = 7461086: Power Element Bush, M4, 12, TH; Manufacturer: Wurth Elektronik; SymbolCreator: a0799628; CompType: Screw Terminal; Pitch_mm: 2.54; Gender: Female
J8 = 282834-2: Terminal Block, 2x1, 2.54mm, TH; Manufacturer: TE Connectivity; SymbolCreator: a0412235
R77 = CRCW06030000Z0EA: as R18 on sheet TIDA-00366-E3_Current sense
R100 R101 R120 = CMP-0021875-2: RES, 1.33, 1%, 0.125 W, 0805; Manufacturer: Yageo America; Power_W: 125mW; TempCo: 200 ppm/C; Value_Code: 1R33; U/M: EA; Value: 1.33; EIA_Code: E96; SizeX_mm: 2; SizeY_mm: 1.25; SizeZ_mm: 1.45; Value2: 0.125W; SizeArea_mm2: 2.5; VDC_V: 150V; AEC Category: Q200
R102 R110 R111 R127 = CMP-0025885-5: as R3 on sheet TIDA-00366-E3_Current sense
R103 R106 R107 R116 R117 R125 R131 = CMP-0025886-5: as R1 on sheet TIDA-00366-E3_Current sense
R104 R105 R114 R115 R122 R130 R141 = CMP-0018748-1: RES, 0, 5%, 0.25 W, 1206; Manufacturer: Panasonic; Power_W: 250mW; TempCo: 600 ppm/C; Value_Code: 0000; U/M: EA; Value: 0; EIA_Code: E24; SizeX_mm: 3.2; SizeY_mm: 1.6; SizeZ_mm: 1.35; Value2: 0.25W; SizeArea_mm2: 5.12; VDC_V: 200V; AEC Category: Q200
R108 R109 R118 R119 R126 R132 = CRCW120616R5FKEA: RES, 16.5, 1%, 0.25 W, 1206; Manufacturer: Vishay-Dale; CompType: Resistor; Value: 16.5; Value_Code: 16R5; Tolerance_%: 1; Power_W: 0.25; Value2: 0.25W; VDC_V: 200; TempCo: 100 ppm/C; EIA_Code: E96; U/M: EA; AEC Category: Q200; SizeArea_mm2: 5.12; SizeX_mm: 3.2; SizeY_mm: 1.6; SizeZ_mm: 1.35
R112 R113 R128 = CMP-0022906-5: RES, 20.0 k, 1%, 0.1 W, 0603; Manufacturer: Yageo; Power_W: 100mW; TempCo: 100 ppm/C; Value_Code: 20k0; Value: 20.0k; EIA_Code: E96; Res_ohm: 20k; SizeX_mm: 1.6; SizeY_mm: 0.8; SizeZ_mm: 1; Value2: 0.1W; SizeArea_mm2: 1.28; AEC Qualified: N; VDC_V: 75V; AEC Category: Q200; SizeAreaWB_mm2: 4.68
R121 R123 R124 = PWR4412-2SDR0050F: RES, 0.005, 1%, 5 W, 20.32x4.80mm; Manufacturer: Bourns; CompType: Resistor; Value: 0.005; Value_Code: 5L000; Tolerance_%: 1; Power_W: 5; Value2: 5W; TempCo: 20 ppm/C; EIA_Code: E96; U/M: EA; AEC Category: Q200; AEC Qualified: N
R129 = CMP-0022692-3: RES, 22.0 k, 1%, 0.1 W, AEC-Q200 Grade 0, 0603; Manufacturer: Panasonic; Power_W: 100mW; TempCo: 100 ppm/C; Value_Code: 22k0; U/M: EA; Value: 22.0k; Res_ohm: 22k; SizeX_mm: 1.6; SizeY_mm: 0.8; SizeZ_mm: 1; Value2: 0.1W; SizeArea_mm2: 1.28; AEC Qualified: Y; VDC_V: 50V; AEC Grade: 0; AEC Category: Q200
R133 R139 R140 R142 = CRCW08050000Z0EA: RES, 0, 5%, 0.125 W, 0805; Manufacturer: Vishay-Dale; CompType: Resistor; Value: 0; Value_Code: 0000; Tolerance_%: 5; Power_W: 0.125; Value2: 0.125W; VDC_V: 150; TempCo: 200 ppm/C; EIA_Code: E24; U/M: EA; AEC Category: Q200
R134-R138 = CRCW1206100KJNEA: RES, 100 k, 5%, 0.25 W, 1206; Manufacturer: Vishay-Dale; CompType: Resistor; Value: 100k; Res_ohm: 100000; Tolerance_%: 5; Power_W: 0.25; Value2: 0.25W; VDC_V: 200; TempCo: 200 ppm/C; EIA_Code: E24; U/M: EA; AEC Category: Q200
TP4-TP6 = PAD_100mil-40milhole: 100mil pad, 40mil hole; Manufacturer: Any
U18 U19 U22 = CMP-0083996-1: 4-A, 6-A, 5.7-kVRMS Isolated Dual-Channel Gate Driver with Enable, DWK0014A (SOIC-14); Alternate PartNumber: UCC21530DWKR; Alternate Manufacturer: Texas Instruments; SizeAreaWB_mm2: 151.29; SizeZ_mm: 2.65; SizeX_mm: 10.3; SizeArea_mm2: 106.09; CompType: IC; AEC Qualified: Y
U20 = CMP-0051622-1: Single 2-Input Positive-OR Gate, DBV0005A, LARGE T&R; Manufacturer: Texas Instruments; VCC(Min)(V): 1.65; Sub-Family: OR Gate; Schmitt Trigger: No; VCC(Max)(V): 5.5; Technology Family: LVC; F @ Nom Voltage(Max)(Mhz): 150; Input Type: CMOS/TTL; Output Drive (IOL/IOH)(Max)(mA): 32/-32; Rating: Catalog; Output Type: CMOS; Voltage(Nom)(V): 1.8,2.5,3.3,5; Bits(#): 1; tpd @ Nom Voltage(Max)(ns): 7.2,4.4,3.6,3.4; ICC @ Nom Voltage(Max)(mA): 0.01; Logic: True
U21 = CMP-0051219-1: Single 3-Input Positive-AND Gate, DBV0006A, LARGE T&R; Manufacturer: Texas Instruments; Output Type: CMOS; Voltage(Nom)(V): 1.8,2.5,3.3,5; ICC @ Nom Voltage(Max)(mA): 0.01; VCC(Min)(V): 1.65; Output Drive (IOL/IOH)(Max)(mA): 32/-32; Schmitt Trigger: No; Input Type: CMOS/TTL; VCC(Max)(V): 5.5; Gate Type: AND; Rating: Catalog; tpd @ Nom Voltage(Max)(ns): 20,7.8,6.2,4.6; Bits(#): 1; F @ Nom Voltage(Max)(Mhz): 150; Logic: True; Technology Family: LVC
U23 = MWI 50-12T7T: IGBT MOD 1200V 85A E2-Pack; Manufacturer: IXYS; SymbolCreator: Altium

## Sheet TIDA-00366-E3_DC BUS and TEMP Sense.SchDoc: DC Bus and TEMP sense
size 431 x 279 mm; Date: Not shown in title block; ApprovedBy: Not shown in title block; CheckedBy: Not shown in title block; Author: Not shown in title block; CompanyName: Not shown in title block; DrawnBy: NN; Engineer: Not shown in title block; Organization: Not shown in title block; Address1: Not shown in title block; Address2: Not shown in title block; Address3: Not shown in title block; Address4: Not shown in title block; DocumentNumber: 1; Revision: Use project parameter SCH_Rev; SheetNumber: 4; SheetTotal: 6; PageSetup: Record=PageOptions¦CenterHorizontal=True¦CenterVertical=True¦PrintScale=1.00¦XCorrection=1.00¦YCorrection=1.00¦PrintKind=0¦BorderSize=5000000¦LeftOffset=0¦BottomOffset=0¦Orientation=2¦PaperLength=1000¦PaperWidth=1000¦Scale=100¦PaperSource=15¦PrintQuality=600¦MediaType=1¦DitherType=10¦PaperKind=Letter¦PrintScaleMode=1
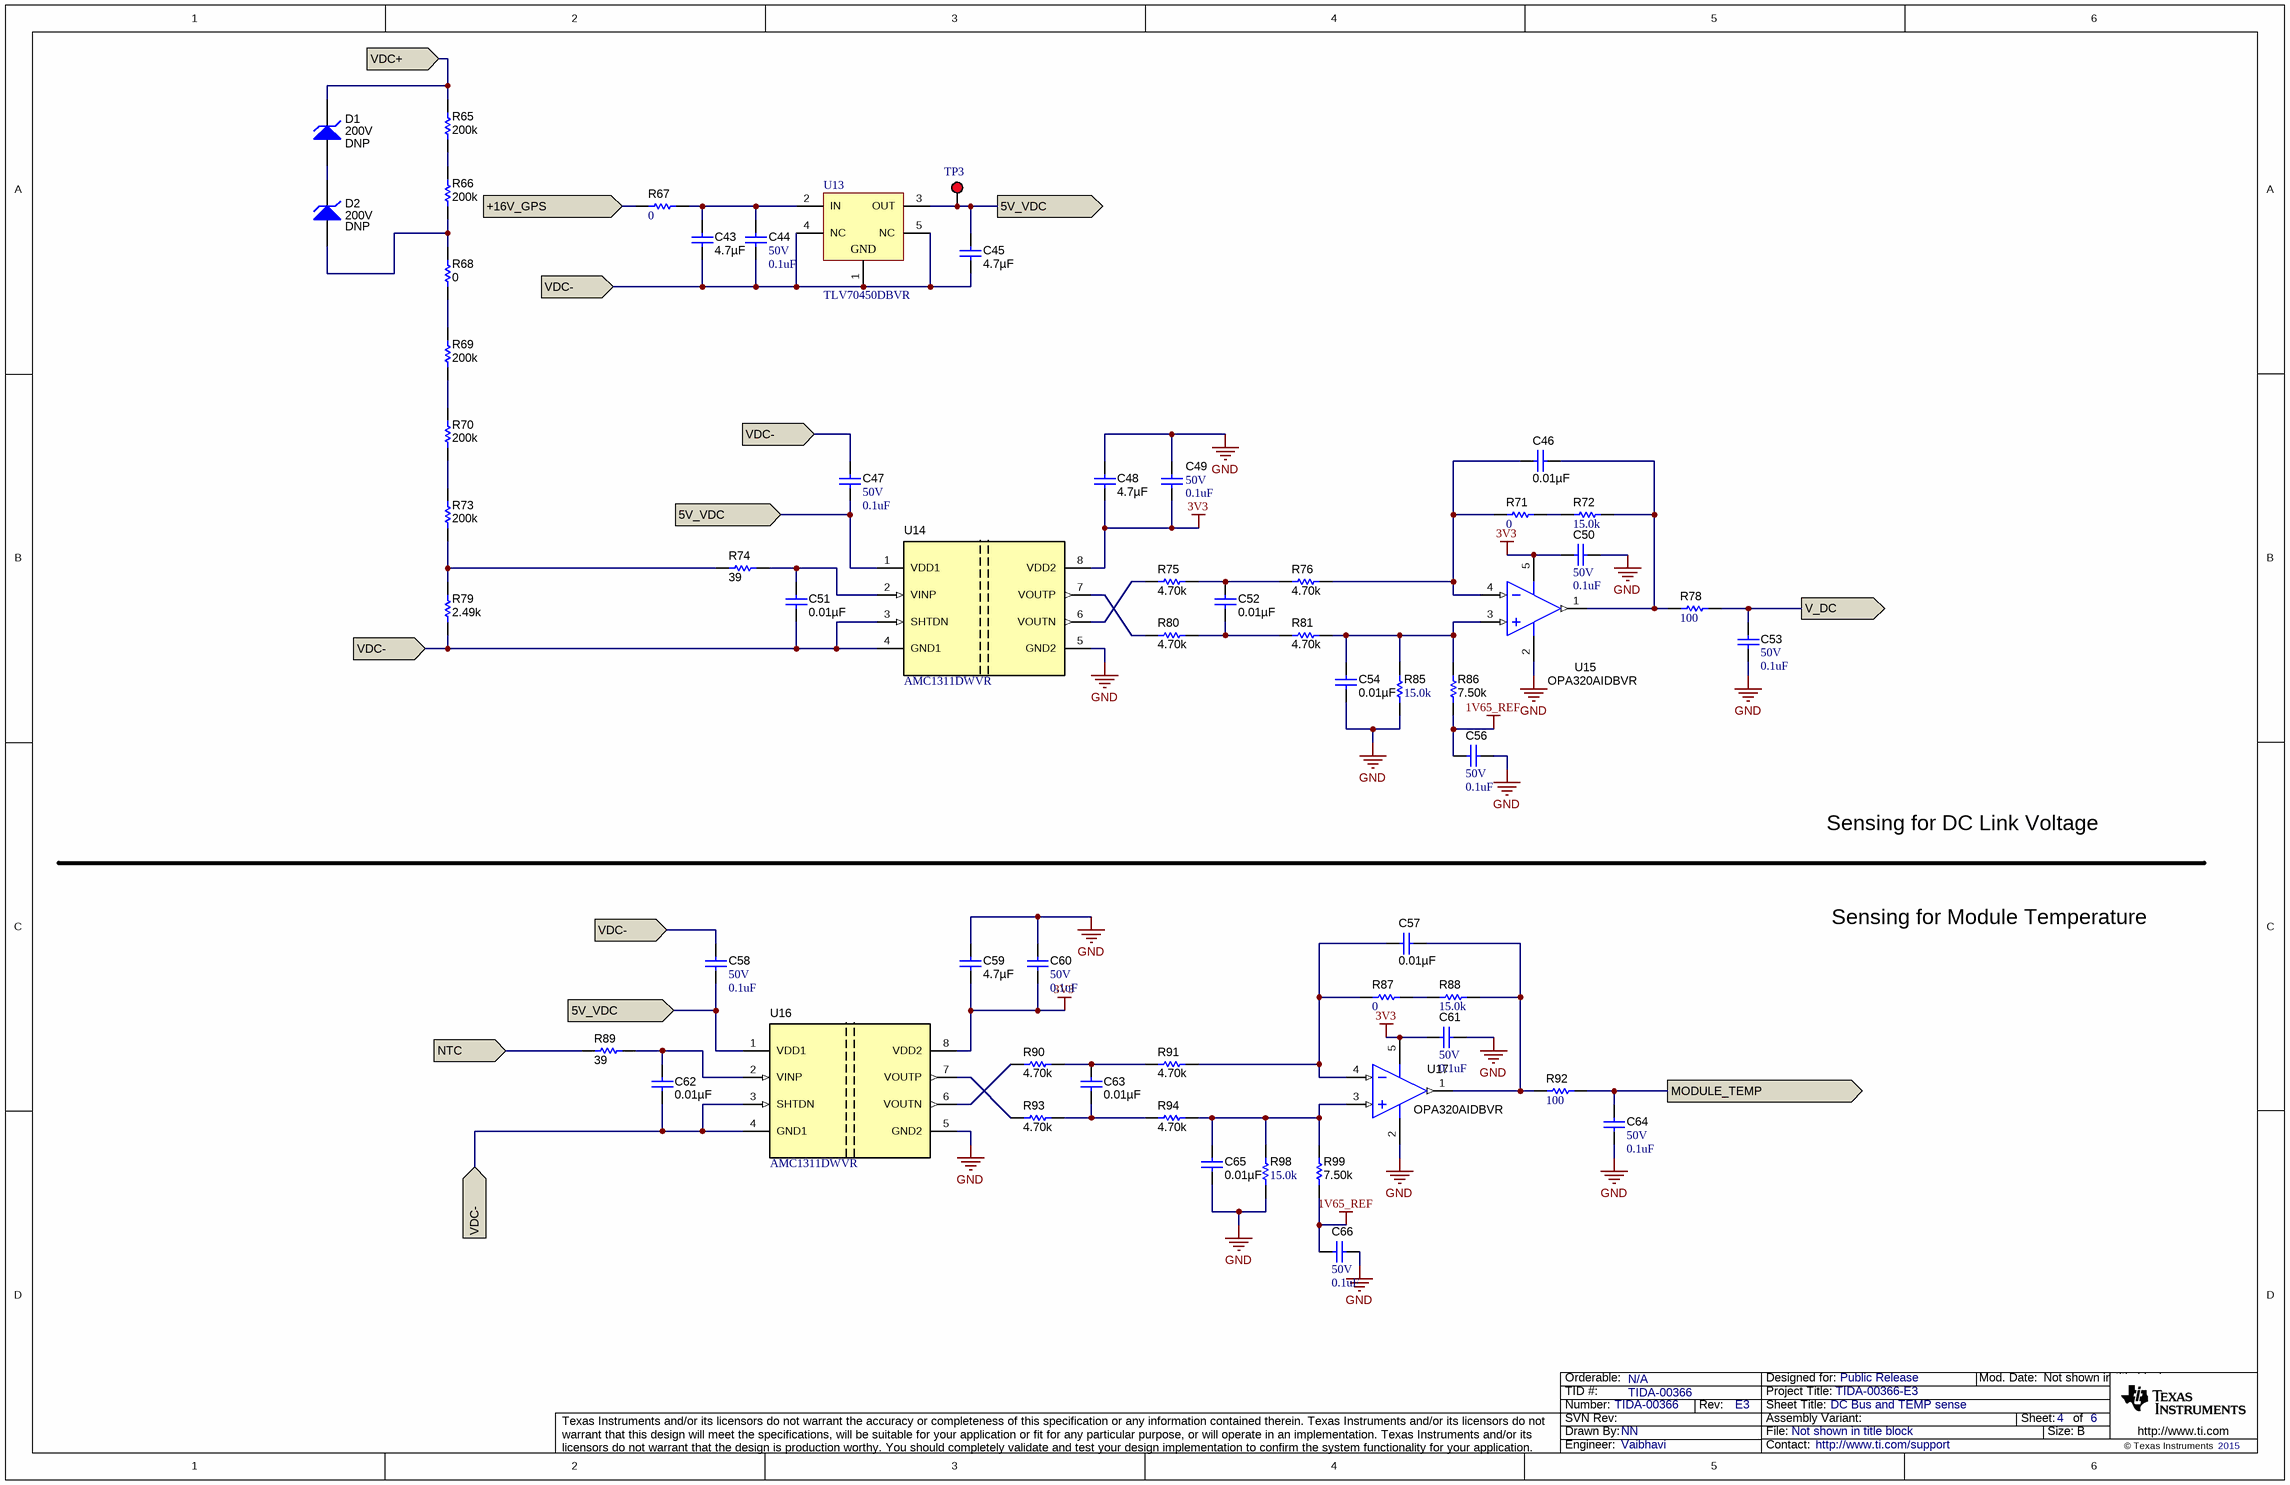
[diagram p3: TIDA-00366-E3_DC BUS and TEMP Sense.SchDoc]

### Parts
C43  ValueDisplayed: 4.7µF  [0805_HV]  (hidden comment: C2012X5R1H475K125AB)
C44  VDC_V: 50V  ValueDisplayed: 0.1uF  [0603]  (hidden comment: GCM188R71H104KA57D)
C45  ValueDisplayed: 4.7µF  [0805_HV]  (hidden comment: C2012X5R1H475K125AB)
C46  ValueDisplayed: 0.01µF  [0603]  (hidden comment: 885012206040)
C47  VDC_V: 50V  ValueDisplayed: 0.1uF  [0603]  (hidden comment: GCM188R71H104KA57D)
C48  ValueDisplayed: 4.7µF  [0805_HV]  (hidden comment: C2012X5R1H475K125AB)
C49  VDC_V: 50V  ValueDisplayed: 0.1uF  [0603]  (hidden comment: GCM188R71H104KA57D)
C50  VDC_V: 50V  ValueDisplayed: 0.1uF  [0603]  (hidden comment: GCM188R71H104KA57D)
C51  ValueDisplayed: 0.01µF  [0603]  (hidden comment: 885012206040)
C52  ValueDisplayed: 0.01µF  [0603]  (hidden comment: 885012206040)
C53  VDC_V: 50V  ValueDisplayed: 0.1uF  [0603]  (hidden comment: GCM188R71H104KA57D)
C54  ValueDisplayed: 0.01µF  [0603]  (hidden comment: 885012206040)
C56  VDC_V: 50V  ValueDisplayed: 0.1uF  [0603]  (hidden comment: GCM188R71H104KA57D)
C57  ValueDisplayed: 0.01µF  [0603]  (hidden comment: 885012206040)
C58  VDC_V: 50V  ValueDisplayed: 0.1uF  [0603]  (hidden comment: GCM188R71H104KA57D)
C59  ValueDisplayed: 4.7µF  [0805_HV]  (hidden comment: C2012X5R1H475K125AB)
C60  VDC_V: 50V  ValueDisplayed: 0.1uF  [0603]  (hidden comment: GCM188R71H104KA57D)
C61  VDC_V: 50V  ValueDisplayed: 0.1uF  [0603]  (hidden comment: GCM188R71H104KA57D)
C62  ValueDisplayed: 0.01µF  [0603]  (hidden comment: 885012206040)
C63  ValueDisplayed: 0.01µF  [0603]  (hidden comment: 885012206040)
C64  VDC_V: 50V  ValueDisplayed: 0.1uF  [0603]  (hidden comment: GCM188R71H104KA57D)
C65  ValueDisplayed: 0.01µF  [0603]  (hidden comment: 885012206040)
C66  VDC_V: 50V  ValueDisplayed: 0.1uF  [0603]  (hidden comment: GCM188R71H104KA57D)
D1  value 200V  [SMB]  (hidden comment: 1SMB5956BT3G)
D2  value 200V  [SMB]  (hidden comment: 1SMB5956BT3G)
R65  ValueDisplayed: 200k  [1206]  (hidden comment: RC1206FR-07200KL)
R66  ValueDisplayed: 200k  [1206]  (hidden comment: RC1206FR-07200KL)
R67  ValueDisplayed: 0  [0603]  (hidden comment: RC0603JR-070RL)
R68  ValueDisplayed: 0  [1206]  (hidden comment: MCR18EZHJ000)
R69  ValueDisplayed: 200k  [1206]  (hidden comment: RC1206FR-07200KL)
R70  ValueDisplayed: 200k  [1206]  (hidden comment: RC1206FR-07200KL)
R71  ValueDisplayed: 0  [0603]  (hidden comment: RC0603JR-070RL)
R72  ValueDisplayed: 15.0k  [0603]  (hidden comment: RC0603FR-0715KL)
R73  ValueDisplayed: 200k  [1206]  (hidden comment: RC1206FR-07200KL)
R74  ValueDisplayed: 39  [0603]  (hidden comment: CRCW060339R0JNEA)
R75  ValueDisplayed: 4.70k  [0603]  (hidden comment: RC0603FR-074K7L)
R76  ValueDisplayed: 4.70k  [0603]  (hidden comment: RC0603FR-074K7L)
R78  ValueDisplayed: 100  [0603]  (hidden comment: RC0603FR-07100RL)
R79  ValueDisplayed: 2.49k  [0603]  (hidden comment: RC0603FR-072K49L)
R80  ValueDisplayed: 4.70k  [0603]  (hidden comment: RC0603FR-074K7L)
R81  ValueDisplayed: 4.70k  [0603]  (hidden comment: RC0603FR-074K7L)
R85  ValueDisplayed: 15.0k  [0603]  (hidden comment: RC0603FR-0715KL)
R86  ValueDisplayed: 7.50k  [0603]  (hidden comment: ERJ-3EKF7501V)
R87  ValueDisplayed: 0  [0603]  (hidden comment: RC0603JR-070RL)
R88  ValueDisplayed: 15.0k  [0603]  (hidden comment: RC0603FR-0715KL)
R89  ValueDisplayed: 39  [0603]  (hidden comment: CRCW060339R0JNEA)
R90  ValueDisplayed: 4.70k  [0603]  (hidden comment: RC0603FR-074K7L)
R91  ValueDisplayed: 4.70k  [0603]  (hidden comment: RC0603FR-074K7L)
R92  ValueDisplayed: 100  [0603]  (hidden comment: RC0603FR-07100RL)
R93  ValueDisplayed: 4.70k  [0603]  (hidden comment: RC0603FR-074K7L)
R94  ValueDisplayed: 4.70k  [0603]  (hidden comment: RC0603FR-074K7L)
R98  ValueDisplayed: 15.0k  [0603]  (hidden comment: RC0603FR-0715KL)
R99  ValueDisplayed: 7.50k  [0603]  (hidden comment: ERJ-3EKF7501V)
TP3  5000  [Keystone5000]  (value not drawn)
U13  TLV70450DBVR  [DBV0005A_N]
U14  AMC1311DWVR  [DWV0008A]
U15  OPA320AIDBVR  [DBV0005A_N]
U16  AMC1311DWVR  [DWV0008A]
U17  OPA320AIDBVR  [DBV0005A_N]

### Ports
5V_VDC (in), 5V_VDC (out), +16V_GPS (in), MODULE_TEMP (out), NTC (in), V_DC (out), VDC+ (in), VDC- (in)

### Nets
1V65_REF: C56.2 C66.2 R86.1 R99.1
3V3: C48.2 C49.2 C50.2 C59.2 C60.2 C61.2 U14.8(VDD2) U15.5(V+) U16.8(VDD2) U17.5(V+)  [project net VCCI]
GND: C48.1 C49.1 C50.1 C53.2 C54.2 C56.1 C59.1 C60.1 C61.1 C64.2 C65.2 C66.1 R85.1 R98.1 U14.5(GND2) U15.2(V-) U16.5(GND2) U17.2(V-)
5V_VDC: C45.1 C47.2 C58.2 TP3.1 U13.3(OUT) U14.1(VDD1) U16.1(VDD1) ; port 5V_VDC
+16V_GPS: R67.1 ; port +16V_GPS
MODULE_TEMP: C64.1 R92.2 ; port MODULE_TEMP
NTC: R89.1 ; port NTC
V_DC: C53.1 R78.2 ; port V_DC
VDC+: D1.1(K) R65.2 ; port VDC+
VDC-: C43.2 C44.2 C45.2 C47.1 C51.2 C58.1 C62.2 R79.1 U13.1(GND) U13.4(NC) U13.5(NC) U14.3(SHTDN) U14.4(GND1) U16.3(SHTDN) U16.4(GND1) ; port VDC-
NetC43_1: C43.1 C44.1 R67.2 U13.2(IN)
NetC46_1: C46.1 R71.1 R76.2 U15.4(IN-)
NetC46_2: C46.2 R72.2 R78.1 U15.1(OUT)
NetC51_1: C51.1 R74.2 U14.2(VINP)
NetC52_1: C52.1 R75.2 R76.1
NetC52_2: C52.2 R80.2 R81.1
NetC54_1: C54.1 R81.2 R85.2 R86.2 U15.3(IN+)
NetC57_1: C57.1 R87.1 R91.2 U17.4(IN-)
NetC57_2: C57.2 R88.2 R92.1 U17.1(OUT)
NetC62_1: C62.1 R89.2 U16.2(VINP)
NetC63_1: C63.1 R90.2 R91.1
NetC63_2: C63.2 R93.2 R94.1
NetC65_1: C65.1 R94.2 R98.2 R99.2 U17.3(IN+)
NetD1_2: D1.2(A) D2.1(K)
NetD2_2: D2.2(A) R66.1 R68.2
NetR65_1: R65.1 R66.2
NetR68_1: R68.1 R69.2
NetR69_1: R69.1 R70.2
NetR70_1: R70.1 R73.2
NetR71_2: R71.2 R72.1
NetR73_1: R73.1 R74.1 R79.2
NetR75_1: R75.1 U14.6(VOUTN)
NetR80_1: R80.1 U14.7(VOUTP)
NetR87_2: R87.2 R88.1
NetR90_1: R90.1 U16.6(VOUTN)
NetR93_1: R93.1 U16.7(VOUTP)

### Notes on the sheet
- Sensing for DC Link Voltage
- Sensing for Module Temperature

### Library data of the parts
C43 C45 C48 C59 = C2012X5R1H475K125AB: as C4 on sheet TIDA-00366-E3_Current sense
C44 C47 C49 C50 C53 C56 C58 C60 C61 C64 C66 = CMP-0007144-4: as C5 on sheet TIDA-00366-E3_Current sense
C46 C51 C52 C54 C57 C62 C63 C65 = 885012206040: CAP, CERM, 0.01 µF, 16 V, +/- 10%, X7R, 0603; Manufacturer: Wurth Elektronik; Polarized: N; CompType: Capacitor; Value: 0.01uF; U/M: EA; Cap_F: 0.00000001; Tolerance_%: 10; Value1: Unknown; VDC_V: 16; Value2: 16V; TaMin_C: -55; TaMax_C: 125; AEC Category: Q200
D1 D2 = 1SMB5956BT3G: Diode, Zener, 200 V, 550 mW, SMB; Manufacturer: ON Semiconductor; SymbolCreator: a0412235; U/M: EA; Power_W: 0.55; Vz_V: 200; Value1: 0.55W; RJA_CperW: 226; AEC Category: Q101
R65 R66 R69 R70 R73 = CMP-0018060-2: RES, 200 k, 1%, 0.25 W, 1206; Manufacturer: Yageo America; Power_W: 250mW; TempCo: 100 ppm/C; U/M: EA; Value: 200k; EIA_Code: E96; SizeX_mm: 3.2; SizeY_mm: 1.6; SizeZ_mm: 1.35; Value2: 0.25W; SizeArea_mm2: 5.12; VDC_V: 200V; AEC Category: Q200
R67 R71 R87 = CMP-0025885-5: as R3 on sheet TIDA-00366-E3_Current sense
R68 = CMP-0018756-2: RES, 0, 5%, 0.25 W, 1206; Manufacturer: Rohm; Power_W: 250mW; TempCo: 200 ppm/C; Value_Code: 0000; U/M: EA; Value: 0; EIA_Code: E24; SizeX_mm: 3.2; SizeY_mm: 1.6; SizeZ_mm: 1.35; Value2: 0.25W; SizeArea_mm2: 5.12; VDC_V: 200V; AEC Category: Q200
R72 R85 R88 R98 = CMP-0022816-5: RES, 15.0 k, 1%, 0.1 W, 0603; Manufacturer: Yageo; Power_W: 100mW; TempCo: 100 ppm/C; Value_Code: 15k0; Value: 15.0k; EIA_Code: E96; Res_ohm: 15k; SizeX_mm: 1.6; SizeY_mm: 0.8; SizeZ_mm: 1; Value2: 0.1W; SizeArea_mm2: 1.28; AEC Qualified: N; VDC_V: 75V; AEC Category: Q200; SizeAreaWB_mm2: 4.68
R74 R89 = CRCW060339R0JNEA: RES, 39, 5%, 0.1 W, 0603; Manufacturer: Vishay-Dale; CompType: Resistor; Value: 39; Value_Code: 39R0; Tolerance_%: 5; Power_W: 0.1; Value2: 0.1W; VDC_V: 75; TempCo: 200 ppm/C; EIA_Code: E24; U/M: EA; AEC Category: Q200
R75 R76 R80 R81 R90 R91 R93 R94 = RC0603FR-074K7L: as R12 on sheet TIDA-00366-E3_Current sense
R78 R92 = CMP-0022736-4: as R5 on sheet TIDA-00366-E3_Current sense
R79 = CMP-0022990-5: RES, 2.49 k, 1%, 0.1 W, 0603; Manufacturer: Yageo; Power_W: 100mW; TempCo: 100 ppm/C; Value_Code: 2k49; Value: 2.49k; EIA_Code: E96; SizeX_mm: 1.6; SizeY_mm: 0.8; SizeZ_mm: 1; Value2: 0.1W; SizeArea_mm2: 1.28; AEC Qualified: N; VDC_V: 75V; AEC Category: Q200; SizeAreaWB_mm2: 4.68
R86 R99 = ERJ-3EKF7501V: as R21 on sheet TIDA-00366-E3_Current sense
TP3 = 5000: as TP1 on sheet TIDA-00366-E3_Current sense
U13 = CMP-0035558-1: Single Output LDO, 150 mA, Fixed 5 V Output, 2.5 to 24 V Input, with Ultra-Low IQ, 5-pin SOT-23 (DBV), -40 to 125 degC, Green (RoHS & no Sb/Br); Manufacturer: Texas Instruments; Vout Adj(Max)(V): 5; Vin(Min)(V): 2.5; Vin(Max)(V): 24; Accuracy(%): 2; SubFamily: Single Channel LDO; Iout(Max)(A): 0.15; Vdo(Typ)(mV): 400; Iq(Typ)(mA): 0.003
U14 U16 = CMP-0013503-1: Precision, 2-V Input, Reinforced Isolated Amplifier, DWV0008A (SOIC-8); Alternate Manufacturer: Texas Instruments; SizeAreaWB_mm2: 105.975; U/M: EA; SizeZ_mm: 2.8; SizeX_mm: 11.5; SizeY_mm: 5.85; SizeArea_mm2: 67.275; CompType: IC
U15 U17 = OPA320AIDBVR: as U4 on sheet TIDA-00366-E3_Current sense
